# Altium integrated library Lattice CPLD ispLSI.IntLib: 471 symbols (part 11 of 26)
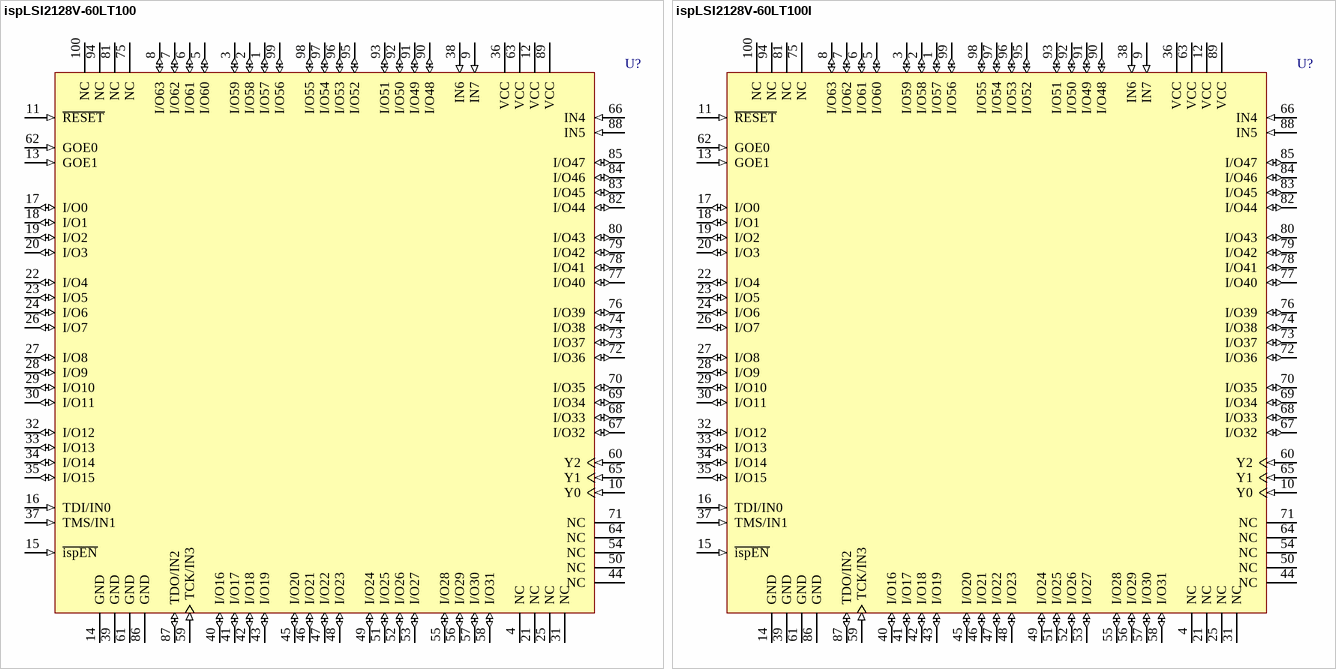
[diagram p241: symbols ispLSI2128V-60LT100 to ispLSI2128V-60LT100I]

## ispLSI2128V-60LT100I
designator U?
3.3V High-Density Programmable Logic
footprint TQFP100_N (Thin QFP, 100-Leads, Body 14x14mm, Pitch 0.5mm, IPC Medium Density)
footprint TQFP100_L (Thin QFP, 100-Leads, Body 14x14mm, Pitch 0.5mm, IPC High Density)
footprint TQFP100_M (Thin QFP, 100-Leads, Body 14x14mm, Pitch 0.5mm, IPC Low Density)
3D model 2128V-TQFP100 (100-Pin Thin Quad Flat Pack (TQFP100))
pins: 1 I/O57 (io), 2 I/O58 (io), 3 I/O59 (io), 4 NC, 5 I/O60 (io), 6 I/O61 (io), 7 I/O62 (io), 8 I/O63 (io), 9 IN7 (in), 10 Y0 (in), 11 ~{RESET} (in), 12 VCC (power), 13 GOE1 (in), 14 GND (power), 15 ~{ispEN} (in), 16 TDI/IN0 (in), 17 I/O0 (io), 18 I/O1 (io), 19 I/O2 (io), 20 I/O3 (io), 21 NC, 22 I/O4 (io), 23 I/O5 (io), 24 I/O6 (io), 25 NC, 26 I/O7 (io), 27 I/O8 (io), 28 I/O9 (io), 29 I/O10 (io), 30 I/O11 (io), 31 NC, 32 I/O12 (io), 33 I/O13 (io), 34 I/O14 (io), 35 I/O15 (io), 36 VCC (power), 37 TMS/IN1 (in), 38 IN6 (in), 39 GND (power), 40 I/O16 (io), 41 I/O17 (io), 42 I/O18 (io), 43 I/O19 (io), 44 NC, 45 I/O20 (io), 46 I/O21 (io), 47 I/O22 (io), 48 I/O23 (io), 49 I/O24 (io), 50 NC, 51 I/O25 (io), 52 I/O26 (io), 53 I/O27 (io), 54 NC, 55 I/O28 (io), 56 I/O29 (io), 57 I/O30 (io), 58 I/O31 (io), 59 TCK/IN3 (in), 60 Y2 (in), 61 GND (power), 62 GOE0 (in), 63 VCC (power), 64 NC, 65 Y1 (in), 66 IN4 (in), 67 I/O32 (io), 68 I/O33 (io), 69 I/O34 (io), 70 I/O35 (io), 71 NC, 72 I/O36 (io), 73 I/O37 (io), 74 I/O38 (io), 75 NC, 76 I/O39 (io), 77 I/O40 (io), 78 I/O41 (io), 79 I/O42 (io), 80 I/O43 (io), 81 NC, 82 I/O44 (io), 83 I/O45 (io), 84 I/O46 (io), 85 I/O47 (io), 86 GND (power), 87 TDO/IN2 (io), 88 IN5 (in), 89 VCC (power), 90 I/O48 (io), 91 I/O49 (io), 92 I/O50 (io), 93 I/O51 (io), 94 NC, 95 I/O52 (io), 96 I/O53 (io), 97 I/O54 (io), 98 I/O55 (io), 99 I/O56 (io), 100 NC

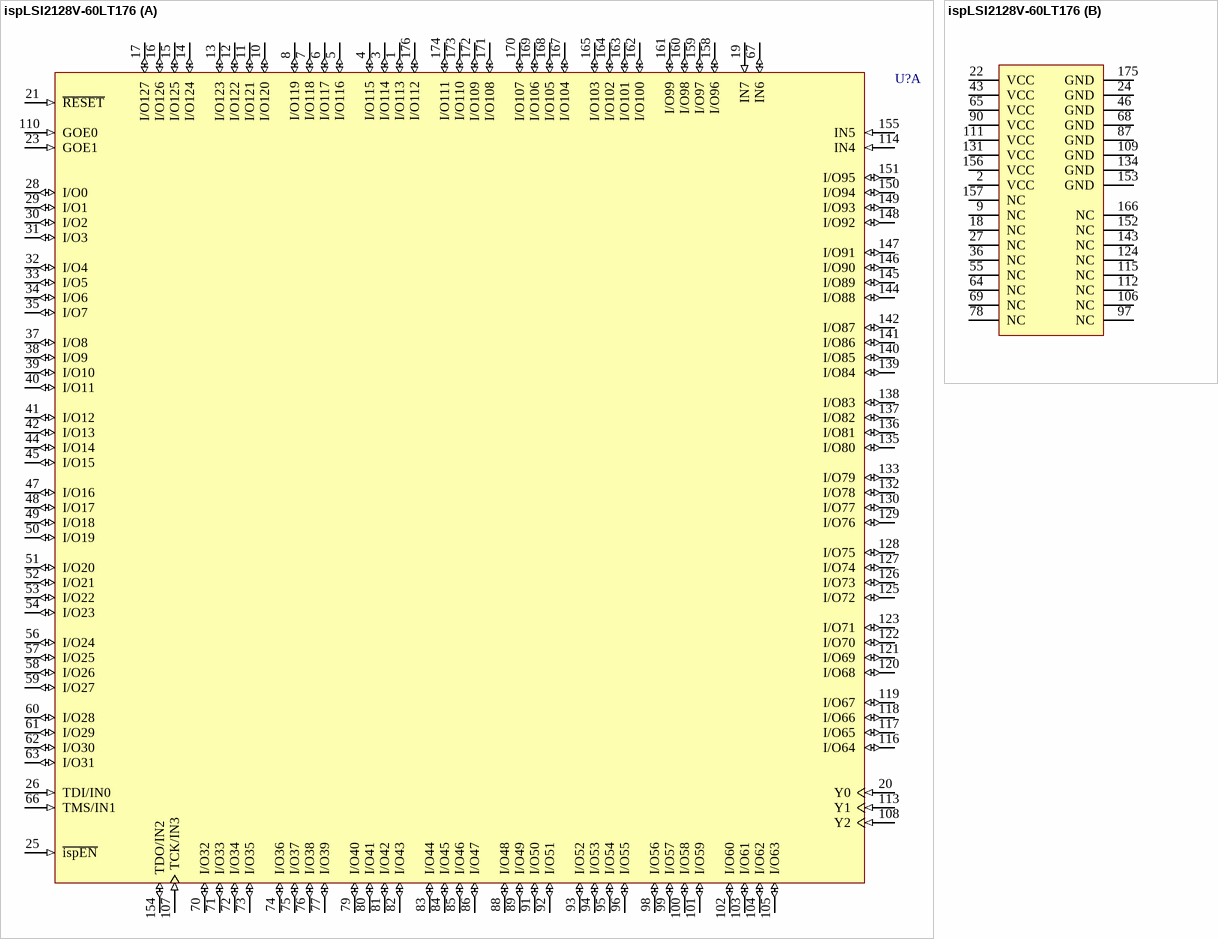
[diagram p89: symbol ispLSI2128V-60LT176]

## ispLSI2128V-60LT176
designator U?
3.3V High-Density Programmable Logic
footprint TQFP176_N (Thin QFP, 176-Leads, Body 24x24mm, Pitch 0.5mm, IPC Medium Density)
footprint TQFP176_L (Thin QFP, 176-Leads, Body 24x24mm, Pitch 0.5mm, IPC High Density)
footprint TQFP176_M (Thin QFP, 176-Leads, Body 24x24mm, Pitch 0.5mm, IPC Low Density)
3D model 2128V-TQFP176 (176-Pin Thin Quad Flat Pack 0.5 mm Pitch)
part A pins: 1 I/O113 (io), 3 I/O114 (io), 4 I/O115 (io), 5 I/O116 (io), 6 I/O117 (io), 7 I/O118 (io), 8 I/O119 (io), 10 I/O120 (io), 11 I/O121 (io), 12 I/O122 (io), 13 I/O123 (io), 14 I/O124 (io), 15 I/O125 (io), 16 I/O126 (io), 17 I/O127 (io), 19 IN7 (in), 20 Y0 (in), 21 ~{RESET} (in), 23 GOE1 (in), 25 ~{ispEN} (in), 26 TDI/IN0 (in), 28 I/O0 (io), 29 I/O1 (io), 30 I/O2 (io), 31 I/O3 (io), 32 I/O4 (io), 33 I/O5 (io), 34 I/O6 (io), 35 I/O7 (io), 37 I/O8 (io), 38 I/O9 (io), 39 I/O10 (io), 40 I/O11 (io), 41 I/O12 (io), 42 I/O13 (io), 44 I/O14 (io), 45 I/O15 (io), 47 I/O16 (io), 48 I/O17 (io), 49 I/O18 (io), 50 I/O19 (io), 51 I/O20 (io), 52 I/O21 (io), 53 I/O22 (io), 54 I/O23 (io), 56 I/O24 (io), 57 I/O25 (io), 58 I/O26 (io), 59 I/O27 (io), 60 I/O28 (io), 61 I/O29 (io), 62 I/O30 (io), 63 I/O31 (io), 66 TMS/IN1 (in), 67 IN6 (io), 70 I/O32 (io), 71 I/O33 (io), 72 I/O34 (io), 73 I/O35 (io), 74 I/O36 (io), 75 I/O37 (io), 76 I/O38 (io), 77 I/O39 (io), 79 I/O40 (io), 80 I/O41 (io), 81 I/O42 (io), 82 I/O43 (io), 83 I/O44 (io), 84 I/O45 (io), 85 I/O46 (io), 86 I/O47 (io), 88 I/O48 (io), 89 I/O49 (io), 91 I/O50 (io), 92 I/O51 (io), 93 I/O52 (io), 94 I/O53 (io), 95 I/O54 (io), 96 I/O55 (io), 98 I/O56 (io), 99 I/O57 (io), 100 I/O58 (io), 101 I/O59 (io), 102 I/O60 (io), 103 I/O61 (io), 104 I/O62 (io), 105 I/O63 (io), 107 TCK/IN3 (in), 108 Y2 (in), 110 GOE0 (in), 113 Y1 (in), 114 IN4 (in), 116 I/O64 (io), 117 I/O65 (io), 118 I/O66 (io), 119 I/O67 (io), 120 I/O68 (io), 121 I/O69 (io), 122 I/O70 (io), 123 I/O71 (io), 125 I/O72 (io), 126 I/O73 (io), 127 I/O74 (io), 128 I/O75 (io), 129 I/O76 (io), 130 I/O77 (io), 132 I/O78 (io), 133 I/O79 (io), 135 I/O80 (io), 136 I/O81 (io), 137 I/O82 (io), 138 I/O83 (io), 139 I/O84 (io), 140 I/O85 (io), 141 I/O86 (io), 142 I/O87 (io), 144 I/O88 (io), 145 I/O89 (io), 146 I/O90 (io), 147 I/O91 (io), 148 I/O92 (io), 149 I/O93 (io), 150 I/O94 (io), 151 I/O95 (io), 154 TDO/IN2 (io), 155 IN5 (in), 158 I/O96 (io), 159 I/O97 (io), 160 I/O98 (io), 161 I/O99 (io), 162 I/O100 (io), 163 I/O101 (io), 164 I/O102 (io), 165 I/O103 (io), 167 I/O104 (io), 168 I/O105 (io), 169 I/O106 (io), 170 I/O107 (io), 171 I/O108 (io), 172 I/O109 (io), 173 I/O110 (io), 174 I/O111 (io), 176 I/O112 (io)
part B pins: 2 VCC (power), 9 NC, 18 NC, 22 VCC (power), 24 GND (power), 27 NC, 36 NC, 43 VCC (power), 46 GND (power), 55 NC, 64 NC, 65 VCC (power), 68 GND (power), 69 NC, 78 NC, 87 GND (power), 90 VCC (power), 97 NC, 106 NC, 109 GND (power), 111 VCC (power), 112 NC, 115 NC, 124 NC, 131 VCC (power), 134 GND (power), 143 NC, 152 NC, 153 GND (power), 156 VCC (power), 157 NC, 166 NC, 175 GND (power)

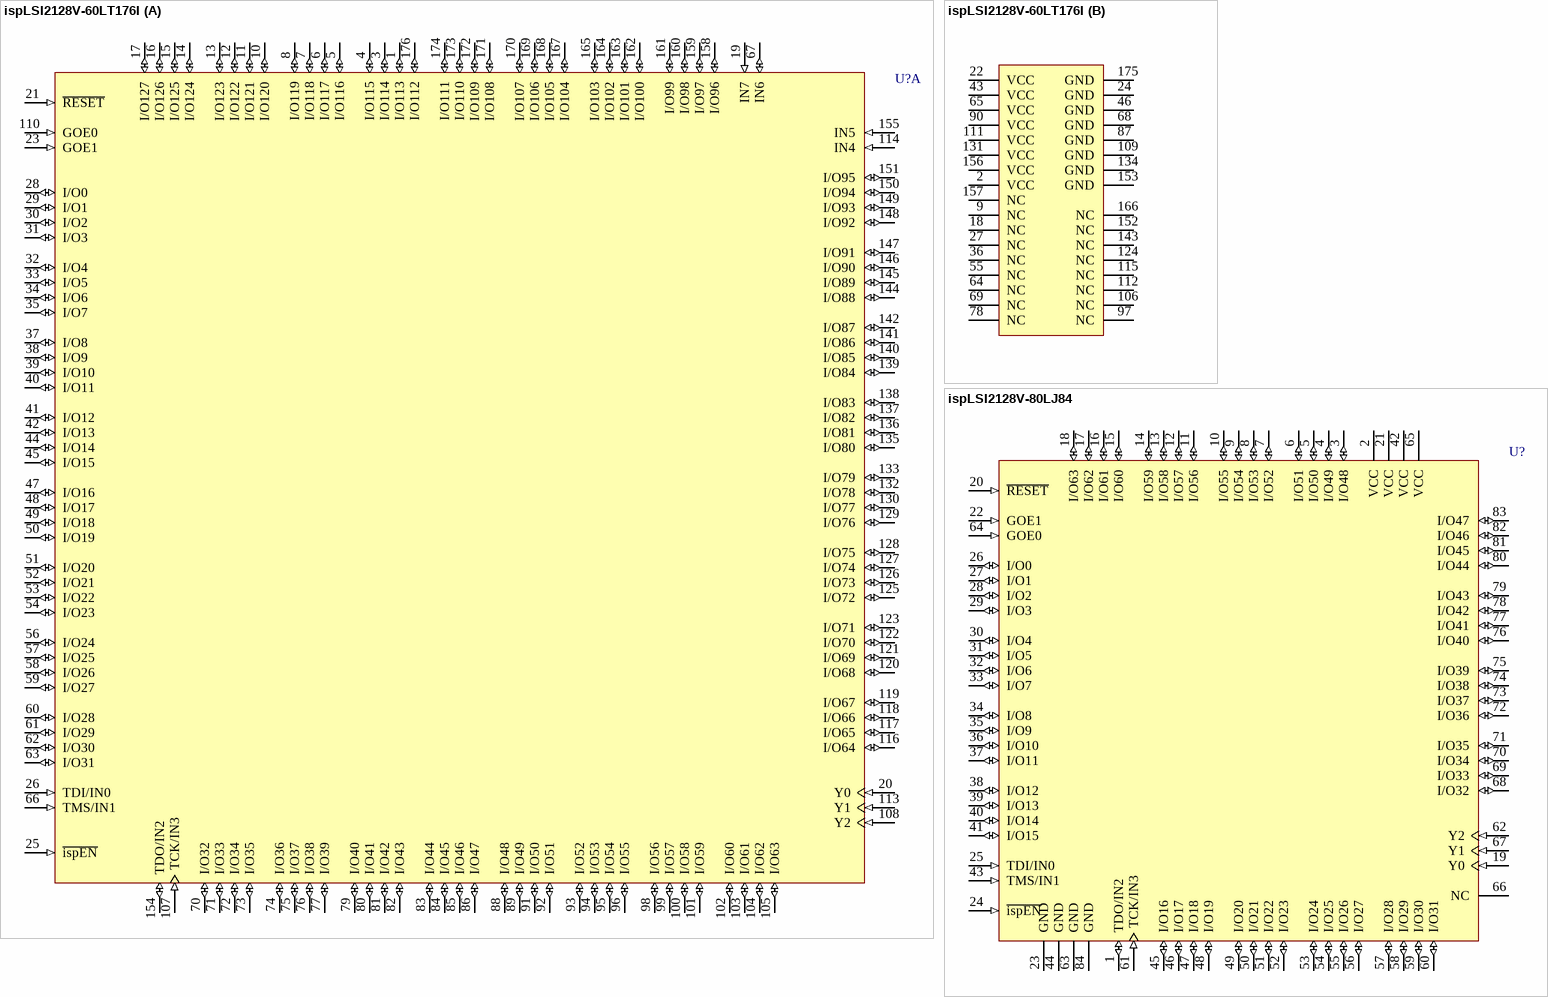
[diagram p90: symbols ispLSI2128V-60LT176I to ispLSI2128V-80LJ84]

## ispLSI2128V-60LT176I
designator U?
3.3V High-Density Programmable Logic
footprint TQFP176_N (Thin QFP, 176-Leads, Body 24x24mm, Pitch 0.5mm, IPC Medium Density)
footprint TQFP176_L (Thin QFP, 176-Leads, Body 24x24mm, Pitch 0.5mm, IPC High Density)
footprint TQFP176_M (Thin QFP, 176-Leads, Body 24x24mm, Pitch 0.5mm, IPC Low Density)
3D model 2128V-TQFP176 (176-Pin Thin Quad Flat Pack 0.5 mm Pitch)
part A pins: 1 I/O113 (io), 3 I/O114 (io), 4 I/O115 (io), 5 I/O116 (io), 6 I/O117 (io), 7 I/O118 (io), 8 I/O119 (io), 10 I/O120 (io), 11 I/O121 (io), 12 I/O122 (io), 13 I/O123 (io), 14 I/O124 (io), 15 I/O125 (io), 16 I/O126 (io), 17 I/O127 (io), 19 IN7 (in), 20 Y0 (in), 21 ~{RESET} (in), 23 GOE1 (in), 25 ~{ispEN} (in), 26 TDI/IN0 (in), 28 I/O0 (io), 29 I/O1 (io), 30 I/O2 (io), 31 I/O3 (io), 32 I/O4 (io), 33 I/O5 (io), 34 I/O6 (io), 35 I/O7 (io), 37 I/O8 (io), 38 I/O9 (io), 39 I/O10 (io), 40 I/O11 (io), 41 I/O12 (io), 42 I/O13 (io), 44 I/O14 (io), 45 I/O15 (io), 47 I/O16 (io), 48 I/O17 (io), 49 I/O18 (io), 50 I/O19 (io), 51 I/O20 (io), 52 I/O21 (io), 53 I/O22 (io), 54 I/O23 (io), 56 I/O24 (io), 57 I/O25 (io), 58 I/O26 (io), 59 I/O27 (io), 60 I/O28 (io), 61 I/O29 (io), 62 I/O30 (io), 63 I/O31 (io), 66 TMS/IN1 (in), 67 IN6 (io), 70 I/O32 (io), 71 I/O33 (io), 72 I/O34 (io), 73 I/O35 (io), 74 I/O36 (io), 75 I/O37 (io), 76 I/O38 (io), 77 I/O39 (io), 79 I/O40 (io), 80 I/O41 (io), 81 I/O42 (io), 82 I/O43 (io), 83 I/O44 (io), 84 I/O45 (io), 85 I/O46 (io), 86 I/O47 (io), 88 I/O48 (io), 89 I/O49 (io), 91 I/O50 (io), 92 I/O51 (io), 93 I/O52 (io), 94 I/O53 (io), 95 I/O54 (io), 96 I/O55 (io), 98 I/O56 (io), 99 I/O57 (io), 100 I/O58 (io), 101 I/O59 (io), 102 I/O60 (io), 103 I/O61 (io), 104 I/O62 (io), 105 I/O63 (io), 107 TCK/IN3 (in), 108 Y2 (in), 110 GOE0 (in), 113 Y1 (in), 114 IN4 (in), 116 I/O64 (io), 117 I/O65 (io), 118 I/O66 (io), 119 I/O67 (io), 120 I/O68 (io), 121 I/O69 (io), 122 I/O70 (io), 123 I/O71 (io), 125 I/O72 (io), 126 I/O73 (io), 127 I/O74 (io), 128 I/O75 (io), 129 I/O76 (io), 130 I/O77 (io), 132 I/O78 (io), 133 I/O79 (io), 135 I/O80 (io), 136 I/O81 (io), 137 I/O82 (io), 138 I/O83 (io), 139 I/O84 (io), 140 I/O85 (io), 141 I/O86 (io), 142 I/O87 (io), 144 I/O88 (io), 145 I/O89 (io), 146 I/O90 (io), 147 I/O91 (io), 148 I/O92 (io), 149 I/O93 (io), 150 I/O94 (io), 151 I/O95 (io), 154 TDO/IN2 (io), 155 IN5 (in), 158 I/O96 (io), 159 I/O97 (io), 160 I/O98 (io), 161 I/O99 (io), 162 I/O100 (io), 163 I/O101 (io), 164 I/O102 (io), 165 I/O103 (io), 167 I/O104 (io), 168 I/O105 (io), 169 I/O106 (io), 170 I/O107 (io), 171 I/O108 (io), 172 I/O109 (io), 173 I/O110 (io), 174 I/O111 (io), 176 I/O112 (io)
part B pins: 2 VCC (power), 9 NC, 18 NC, 22 VCC (power), 24 GND (power), 27 NC, 36 NC, 43 VCC (power), 46 GND (power), 55 NC, 64 NC, 65 VCC (power), 68 GND (power), 69 NC, 78 NC, 87 GND (power), 90 VCC (power), 97 NC, 106 NC, 109 GND (power), 111 VCC (power), 112 NC, 115 NC, 124 NC, 131 VCC (power), 134 GND (power), 143 NC, 152 NC, 153 GND (power), 156 VCC (power), 157 NC, 166 NC, 175 GND (power)

## ispLSI2128V-80LJ84
designator U?
3.3V High-Density Programmable Logic
footprint PLCC84_N (Leaded Chip Carrier, 84-Leads, Body 29.3x29.3mm, Pitch 1.27mm, IPC Medium Density)
footprint PLCC84_L (Leaded Chip Carrier, 84-Leads, Body 29.3x29.3mm, Pitch 1.27mm, IPC High Density)
footprint PLCC84_M (Leaded Chip Carrier, 84-Leads, Body 29.3x29.3mm, Pitch 1.27mm, IPC Low Density)
3D model 2128V-PLCC84 (84-Pin Leaded Chip Carrier 1.27 mm Pitch)
pins: 1 TDO/IN2 (io), 2 VCC (power), 3 I/O48 (io), 4 I/O49 (io), 5 I/O50 (io), 6 I/O51 (io), 7 I/O52 (io), 8 I/O53 (io), 9 I/O54 (io), 10 I/O55 (io), 11 I/O56 (io), 12 I/O57 (io), 13 I/O58 (io), 14 I/O59 (io), 15 I/O60 (io), 16 I/O61 (io), 17 I/O62 (io), 18 I/O63 (io), 19 Y0 (in), 20 ~{RESET} (in), 21 VCC (power), 22 GOE1 (in), 23 GND (power), 24 ~{isp}~{EN} (in), 25 TDI/IN0 (in), 26 I/O0 (io), 27 I/O1 (io), 28 I/O2 (io), 29 I/O3 (io), 30 I/O4 (io), 31 I/O5 (io), 32 I/O6 (io), 33 I/O7 (io), 34 I/O8 (io), 35 I/O9 (io), 36 I/O10 (io), 37 I/O11 (io), 38 I/O12 (io), 39 I/O13 (io), 40 I/O14 (io), 41 I/O15 (io), 42 VCC (power), 43 TMS/IN1 (in), 44 GND (power), 45 I/O16 (io), 46 I/O17 (io), 47 I/O18 (io), 48 I/O19 (io), 49 I/O20 (io), 50 I/O21 (io), 51 I/O22 (io), 52 I/O23 (io), 53 I/O24 (io), 54 I/O25 (io), 55 I/O26 (io), 56 I/O27 (io), 57 I/O28 (io), 58 I/O29 (io), 59 I/O30 (io), 60 I/O31 (io), 61 TCK/IN3 (in), 62 Y2 (in), 63 GND (power), 64 GOE0 (in), 65 VCC (power), 66 NC, 67 Y1 (in), 68 I/O32 (io), 69 I/O33 (io), 70 I/O34 (io), 71 I/O35 (io), 72 I/O36 (io), 73 I/O37 (io), 74 I/O38 (io), 75 I/O39 (io), 76 I/O40 (io), 77 I/O41 (io), 78 I/O42 (io), 79 I/O43 (io), 80 I/O44 (io), 81 I/O45 (io), 82 I/O46 (io), 83 I/O47 (io), 84 GND (power)

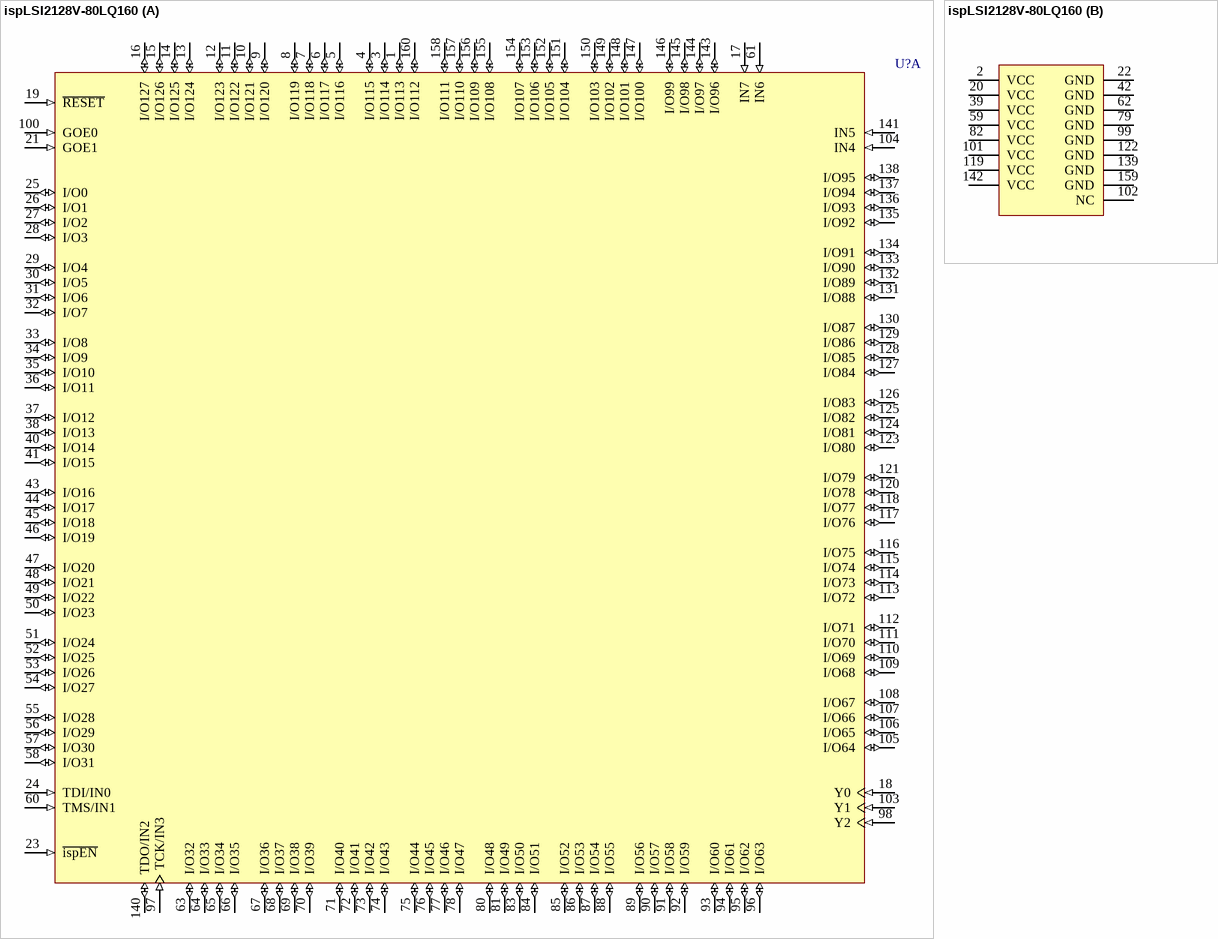
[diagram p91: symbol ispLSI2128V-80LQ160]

## ispLSI2128V-80LQ160
designator U?
3.3V High-Density Programmable Logic
footprint PQFP160_N (QFP, 160-Leads, Body 28 x 28mm, Pitch 0.65mm, IPC Medium Density)
footprint PQFP160_L (QFP, 160-Leads, Body 28 x 28mm, Pitch 0.65mm, IPC High Density)
footprint PQFP160_M (QFP, 160-Leads, Body 28 x 28mm, Pitch 0.65mm, IPC Low Density)
3D model 2128V-PQFP160 (160-Pin Quad Flat Pack 0.65 mm Pitch)
part A pins: 1 I/O113 (io), 3 I/O114 (io), 4 I/O115 (io), 5 I/O116 (io), 6 I/O117 (io), 7 I/O118 (io), 8 I/O119 (io), 9 I/O120 (io), 10 I/O121 (io), 11 I/O122 (io), 12 I/O123 (io), 13 I/O124 (io), 14 I/O125 (io), 15 I/O126 (io), 16 I/O127 (io), 17 IN7 (in), 18 Y0 (in), 19 ~{RESET} (in), 21 GOE1 (in), 23 ~{ispEN} (in), 24 TDI/IN0 (in), 25 I/O0 (io), 26 I/O1 (io), 27 I/O2 (io), 28 I/O3 (io), 29 I/O4 (io), 30 I/O5 (io), 31 I/O6 (io), 32 I/O7 (io), 33 I/O8 (io), 34 I/O9 (io), 35 I/O10 (io), 36 I/O11 (io), 37 I/O12 (io), 38 I/O13 (io), 40 I/O14 (io), 41 I/O15 (io), 43 I/O16 (io), 44 I/O17 (io), 45 I/O18 (io), 46 I/O19 (io), 47 I/O20 (io), 48 I/O21 (io), 49 I/O22 (io), 50 I/O23 (io), 51 I/O24 (io), 52 I/O25 (io), 53 I/O26 (io), 54 I/O27 (io), 55 I/O28 (io), 56 I/O29 (io), 57 I/O30 (io), 58 I/O31 (io), 60 TMS/IN1 (in), 61 IN6 (in), 63 I/O32 (io), 64 I/O33 (io), 65 I/O34 (io), 66 I/O35 (io), 67 I/O36 (io), 68 I/O37 (io), 69 I/O38 (io), 70 I/O39 (io), 71 I/O40 (io), 72 I/O41 (io), 73 I/O42 (io), 74 I/O43 (io), 75 I/O44 (io), 76 I/O45 (io), 77 I/O46 (io), 78 I/O47 (io), 80 I/O48 (io), 81 I/O49 (io), 83 I/O50 (io), 84 I/O51 (io), 85 I/O52 (io), 86 I/O53 (io), 87 I/O54 (io), 88 I/O55 (io), 89 I/O56 (io), 90 I/O57 (io), 91 I/O58 (io), 92 I/O59 (io), 93 I/O60 (io), 94 I/O61 (io), 95 I/O62 (io), 96 I/O63 (io), 97 TCK/IN3 (in), 98 Y2 (in), 100 GOE0 (in), 103 Y1 (in), 104 IN4 (in), 105 I/O64 (io), 106 I/O65 (io), 107 I/O66 (io), 108 I/O67 (io), 109 I/O68 (io), 110 I/O69 (io), 111 I/O70 (io), 112 I/O71 (io), 113 I/O72 (io), 114 I/O73 (io), 115 I/O74 (io), 116 I/O75 (io), 117 I/O76 (io), 118 I/O77 (io), 120 I/O78 (io), 121 I/O79 (io), 123 I/O80 (io), 124 I/O81 (io), 125 I/O82 (io), 126 I/O83 (io), 127 I/O84 (io), 128 I/O85 (io), 129 I/O86 (io), 130 I/O87 (io), 131 I/O88 (io), 132 I/O89 (io), 133 I/O90 (io), 134 I/O91 (io), 135 I/O92 (io), 136 I/O93 (io), 137 I/O94 (io), 138 I/O95 (io), 140 TDO/IN2 (io), 141 IN5 (in), 143 I/O96 (io), 144 I/O97 (io), 145 I/O98 (io), 146 I/O99 (io), 147 I/O100 (io), 148 I/O101 (io), 149 I/O102 (io), 150 I/O103 (io), 151 I/O104 (io), 152 I/O105 (io), 153 I/O106 (io), 154 I/O107 (io), 155 I/O108 (io), 156 I/O109 (io), 157 I/O110 (io), 158 I/O111 (io), 160 I/O112 (io)
part B pins: 2 VCC (power), 20 VCC (power), 22 GND (power), 39 VCC (power), 42 GND (power), 59 VCC (power), 62 GND (power), 79 GND (power), 82 VCC (power), 99 GND (power), 101 VCC (power), 102 NC, 119 VCC (power), 122 GND (power), 139 GND (power), 142 VCC (power), 159 GND (power)

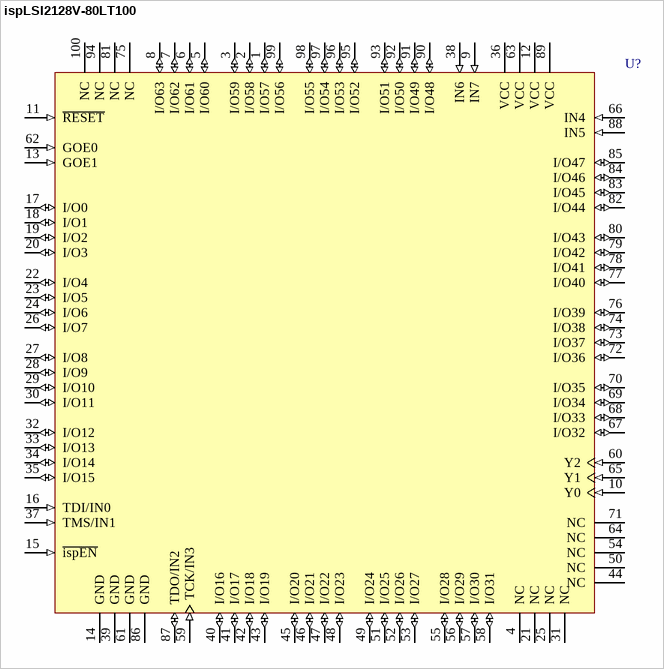
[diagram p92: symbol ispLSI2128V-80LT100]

## ispLSI2128V-80LT100
designator U?
3.3V High-Density Programmable Logic
footprint TQFP100_N (Thin QFP, 100-Leads, Body 14x14mm, Pitch 0.5mm, IPC Medium Density)
footprint TQFP100_L (Thin QFP, 100-Leads, Body 14x14mm, Pitch 0.5mm, IPC High Density)
footprint TQFP100_M (Thin QFP, 100-Leads, Body 14x14mm, Pitch 0.5mm, IPC Low Density)
3D model 2128V-TQFP100 (100-Pin Thin Quad Flat Pack (TQFP100))
pins: 1 I/O57 (io), 2 I/O58 (io), 3 I/O59 (io), 4 NC, 5 I/O60 (io), 6 I/O61 (io), 7 I/O62 (io), 8 I/O63 (io), 9 IN7 (in), 10 Y0 (in), 11 ~{RESET} (in), 12 VCC (power), 13 GOE1 (in), 14 GND (power), 15 ~{ispEN} (in), 16 TDI/IN0 (in), 17 I/O0 (io), 18 I/O1 (io), 19 I/O2 (io), 20 I/O3 (io), 21 NC, 22 I/O4 (io), 23 I/O5 (io), 24 I/O6 (io), 25 NC, 26 I/O7 (io), 27 I/O8 (io), 28 I/O9 (io), 29 I/O10 (io), 30 I/O11 (io), 31 NC, 32 I/O12 (io), 33 I/O13 (io), 34 I/O14 (io), 35 I/O15 (io), 36 VCC (power), 37 TMS/IN1 (in), 38 IN6 (in), 39 GND (power), 40 I/O16 (io), 41 I/O17 (io), 42 I/O18 (io), 43 I/O19 (io), 44 NC, 45 I/O20 (io), 46 I/O21 (io), 47 I/O22 (io), 48 I/O23 (io), 49 I/O24 (io), 50 NC, 51 I/O25 (io), 52 I/O26 (io), 53 I/O27 (io), 54 NC, 55 I/O28 (io), 56 I/O29 (io), 57 I/O30 (io), 58 I/O31 (io), 59 TCK/IN3 (in), 60 Y2 (in), 61 GND (power), 62 GOE0 (in), 63 VCC (power), 64 NC, 65 Y1 (in), 66 IN4 (in), 67 I/O32 (io), 68 I/O33 (io), 69 I/O34 (io), 70 I/O35 (io), 71 NC, 72 I/O36 (io), 73 I/O37 (io), 74 I/O38 (io), 75 NC, 76 I/O39 (io), 77 I/O40 (io), 78 I/O41 (io), 79 I/O42 (io), 80 I/O43 (io), 81 NC, 82 I/O44 (io), 83 I/O45 (io), 84 I/O46 (io), 85 I/O47 (io), 86 GND (power), 87 TDO/IN2 (io), 88 IN5 (in), 89 VCC (power), 90 I/O48 (io), 91 I/O49 (io), 92 I/O50 (io), 93 I/O51 (io), 94 NC, 95 I/O52 (io), 96 I/O53 (io), 97 I/O54 (io), 98 I/O55 (io), 99 I/O56 (io), 100 NC

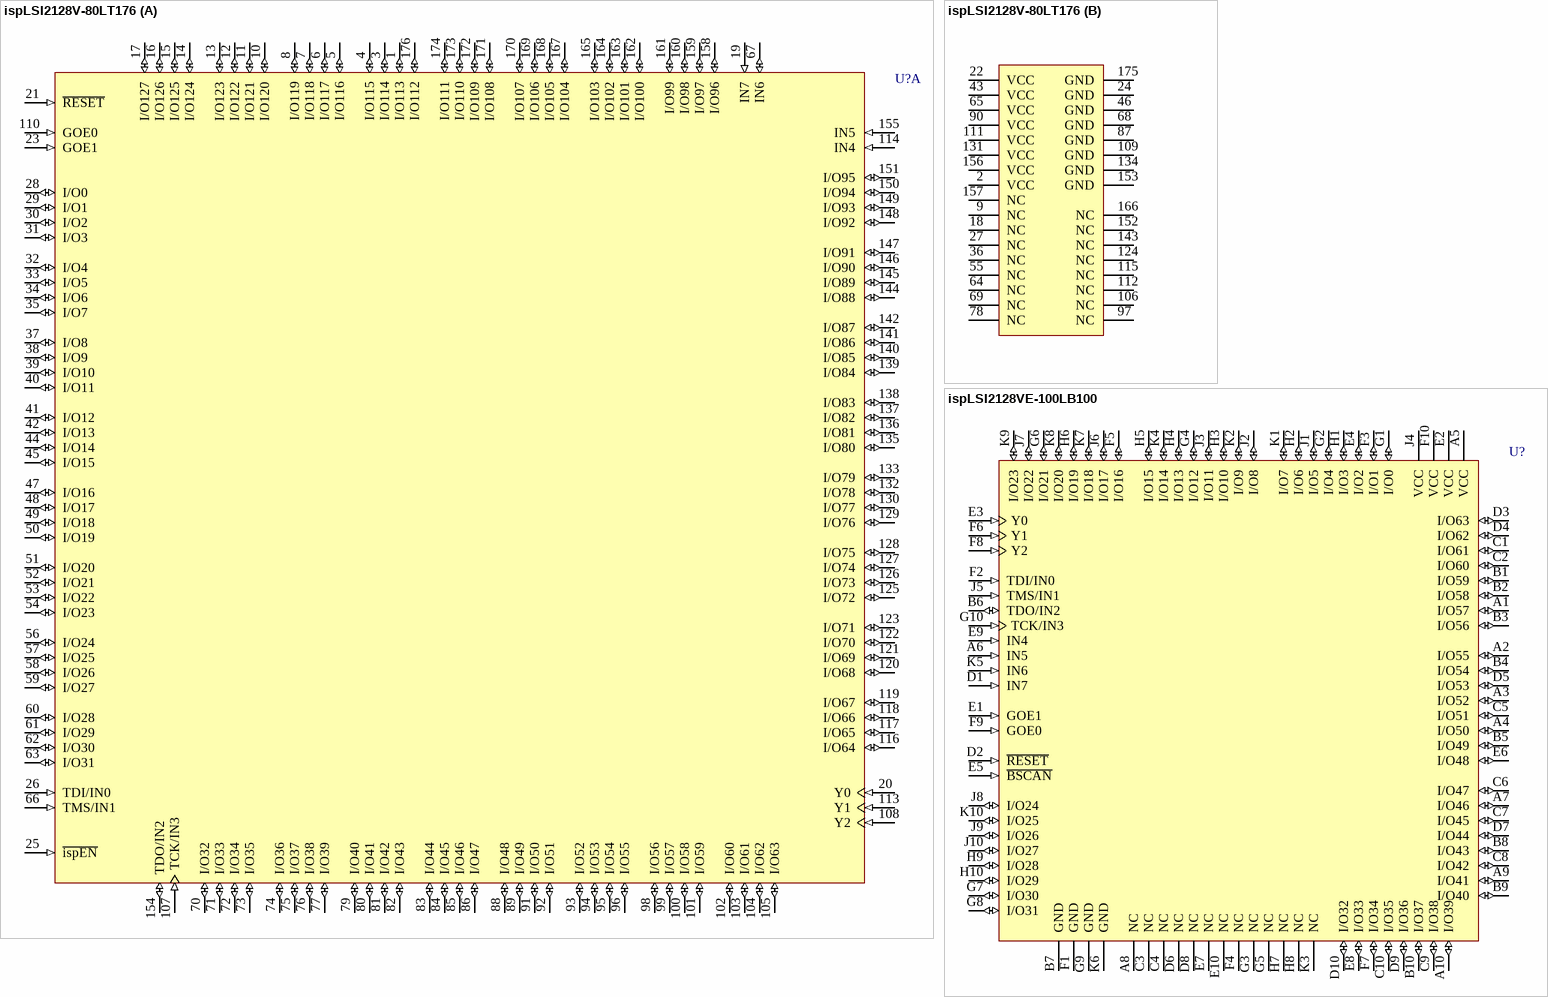
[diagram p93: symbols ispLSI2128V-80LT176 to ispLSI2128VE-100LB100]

## ispLSI2128V-80LT176
designator U?
3.3V High-Density Programmable Logic
footprint TQFP176_N (Thin QFP, 176-Leads, Body 24x24mm, Pitch 0.5mm, IPC Medium Density)
footprint TQFP176_L (Thin QFP, 176-Leads, Body 24x24mm, Pitch 0.5mm, IPC High Density)
footprint TQFP176_M (Thin QFP, 176-Leads, Body 24x24mm, Pitch 0.5mm, IPC Low Density)
3D model 2128V-TQFP176 (176-Pin Thin Quad Flat Pack 0.5 mm Pitch)
part A pins: 1 I/O113 (io), 3 I/O114 (io), 4 I/O115 (io), 5 I/O116 (io), 6 I/O117 (io), 7 I/O118 (io), 8 I/O119 (io), 10 I/O120 (io), 11 I/O121 (io), 12 I/O122 (io), 13 I/O123 (io), 14 I/O124 (io), 15 I/O125 (io), 16 I/O126 (io), 17 I/O127 (io), 19 IN7 (in), 20 Y0 (in), 21 ~{RESET} (in), 23 GOE1 (in), 25 ~{ispEN} (in), 26 TDI/IN0 (in), 28 I/O0 (io), 29 I/O1 (io), 30 I/O2 (io), 31 I/O3 (io), 32 I/O4 (io), 33 I/O5 (io), 34 I/O6 (io), 35 I/O7 (io), 37 I/O8 (io), 38 I/O9 (io), 39 I/O10 (io), 40 I/O11 (io), 41 I/O12 (io), 42 I/O13 (io), 44 I/O14 (io), 45 I/O15 (io), 47 I/O16 (io), 48 I/O17 (io), 49 I/O18 (io), 50 I/O19 (io), 51 I/O20 (io), 52 I/O21 (io), 53 I/O22 (io), 54 I/O23 (io), 56 I/O24 (io), 57 I/O25 (io), 58 I/O26 (io), 59 I/O27 (io), 60 I/O28 (io), 61 I/O29 (io), 62 I/O30 (io), 63 I/O31 (io), 66 TMS/IN1 (in), 67 IN6 (io), 70 I/O32 (io), 71 I/O33 (io), 72 I/O34 (io), 73 I/O35 (io), 74 I/O36 (io), 75 I/O37 (io), 76 I/O38 (io), 77 I/O39 (io), 79 I/O40 (io), 80 I/O41 (io), 81 I/O42 (io), 82 I/O43 (io), 83 I/O44 (io), 84 I/O45 (io), 85 I/O46 (io), 86 I/O47 (io), 88 I/O48 (io), 89 I/O49 (io), 91 I/O50 (io), 92 I/O51 (io), 93 I/O52 (io), 94 I/O53 (io), 95 I/O54 (io), 96 I/O55 (io), 98 I/O56 (io), 99 I/O57 (io), 100 I/O58 (io), 101 I/O59 (io), 102 I/O60 (io), 103 I/O61 (io), 104 I/O62 (io), 105 I/O63 (io), 107 TCK/IN3 (in), 108 Y2 (in), 110 GOE0 (in), 113 Y1 (in), 114 IN4 (in), 116 I/O64 (io), 117 I/O65 (io), 118 I/O66 (io), 119 I/O67 (io), 120 I/O68 (io), 121 I/O69 (io), 122 I/O70 (io), 123 I/O71 (io), 125 I/O72 (io), 126 I/O73 (io), 127 I/O74 (io), 128 I/O75 (io), 129 I/O76 (io), 130 I/O77 (io), 132 I/O78 (io), 133 I/O79 (io), 135 I/O80 (io), 136 I/O81 (io), 137 I/O82 (io), 138 I/O83 (io), 139 I/O84 (io), 140 I/O85 (io), 141 I/O86 (io), 142 I/O87 (io), 144 I/O88 (io), 145 I/O89 (io), 146 I/O90 (io), 147 I/O91 (io), 148 I/O92 (io), 149 I/O93 (io), 150 I/O94 (io), 151 I/O95 (io), 154 TDO/IN2 (io), 155 IN5 (in), 158 I/O96 (io), 159 I/O97 (io), 160 I/O98 (io), 161 I/O99 (io), 162 I/O100 (io), 163 I/O101 (io), 164 I/O102 (io), 165 I/O103 (io), 167 I/O104 (io), 168 I/O105 (io), 169 I/O106 (io), 170 I/O107 (io), 171 I/O108 (io), 172 I/O109 (io), 173 I/O110 (io), 174 I/O111 (io), 176 I/O112 (io)
part B pins: 2 VCC (power), 9 NC, 18 NC, 22 VCC (power), 24 GND (power), 27 NC, 36 NC, 43 VCC (power), 46 GND (power), 55 NC, 64 NC, 65 VCC (power), 68 GND (power), 69 NC, 78 NC, 87 GND (power), 90 VCC (power), 97 NC, 106 NC, 109 GND (power), 111 VCC (power), 112 NC, 115 NC, 124 NC, 131 VCC (power), 134 GND (power), 143 NC, 152 NC, 153 GND (power), 156 VCC (power), 157 NC, 166 NC, 175 GND (power)

## ispLSI2128VE-100LB100
designator U?
3.3V In-System Programmable SuperFAST High Density PLD
footprint caBGA100 (BGA, 100-Leads, Body 10x10mm, Pitch 0.8mm)
3D model 2128VE-caBGA100 (100-Ball Chip Array Ball Grid Array (caBGA100))
pins: A1 I/O57 (io), A2 I/O55 (io), A3 I/O52 (io), A4 I/O50 (io), A5 VCC (power), A6 IN5 (in), A7 I/O46 (io), A8 NC, A9 I/O41 (io), A10 I/O39 (io), B1 I/O59 (io), B2 I/O58 (io), B3 I/O56 (io), B4 I/O54 (io), B5 I/O49 (io), B6 TDO/IN2 (io), B7 GND (power), B8 I/O43 (io), B9 I/O40 (io), B10 I/O37 (io), C1 I/O61 (io), C2 I/O60 (io), C3 NC, C4 NC, C5 I/O51 (io), C6 I/O47 (io), C7 I/O45 (io), C8 I/O42 (io), C9 I/O38 (io), C10 I/O35 (io), D1 IN7 (in), D2 ~{RESET} (in), D3 I/O63 (io), D4 I/O62 (io), D5 I/O53 (io), D6 NC, D7 I/O44 (io), D8 NC, D9 I/O36 (io), D10 I/O32 (io), E1 GOE1 (in), E2 VCC (power), E3 Y0 (in), E4 I/O2 (io), E5 ~{BSCAN} (in), E6 I/O48 (io), E7 NC, E8 I/O33 (io), E9 IN4 (in), E10 NC, F1 GND (power), F2 TDI/IN0 (in), F3 I/O1 (io), F4 NC, F5 I/O16 (io), F6 Y1 (in), F7 I/O34 (io), F8 Y2 (in), F9 GOE0 (in), F10 VCC (power), G1 I/O0 (io), G2 I/O4 (io), G3 NC, G4 I/O12 (io), G5 NC, G6 I/O21 (io), G7 I/O30 (io), G8 I/O31 (io), G9 GND (power), G10 TCK/IN3 (in), H1 I/O3 (io), H2 I/O6 (io), H3 I/O10 (io), H4 I/O13 (io), H5 I/O15 (io), H6 I/O19 (io), H7 NC, H8 NC, H9 I/O28 (io), H10 I/O29 (io), J1 I/O5 (io), J2 I/O8 (io), J3 I/O11 (io), J4 VCC (power), J5 TMS/IN1 (in), J6 I/O17 (io), J7 I/O22 (io), J8 I/O24 (io), J9 I/O26 (io), J10 I/O27 (io), K1 I/O7 (io), K2 I/O9 (io), K3 NC, K4 I/O14 (io), K5 IN6 (in), K6 GND (power), K7 I/O18 (io), K8 I/O20 (io), K9 I/O23 (io), K10 I/O25 (io)

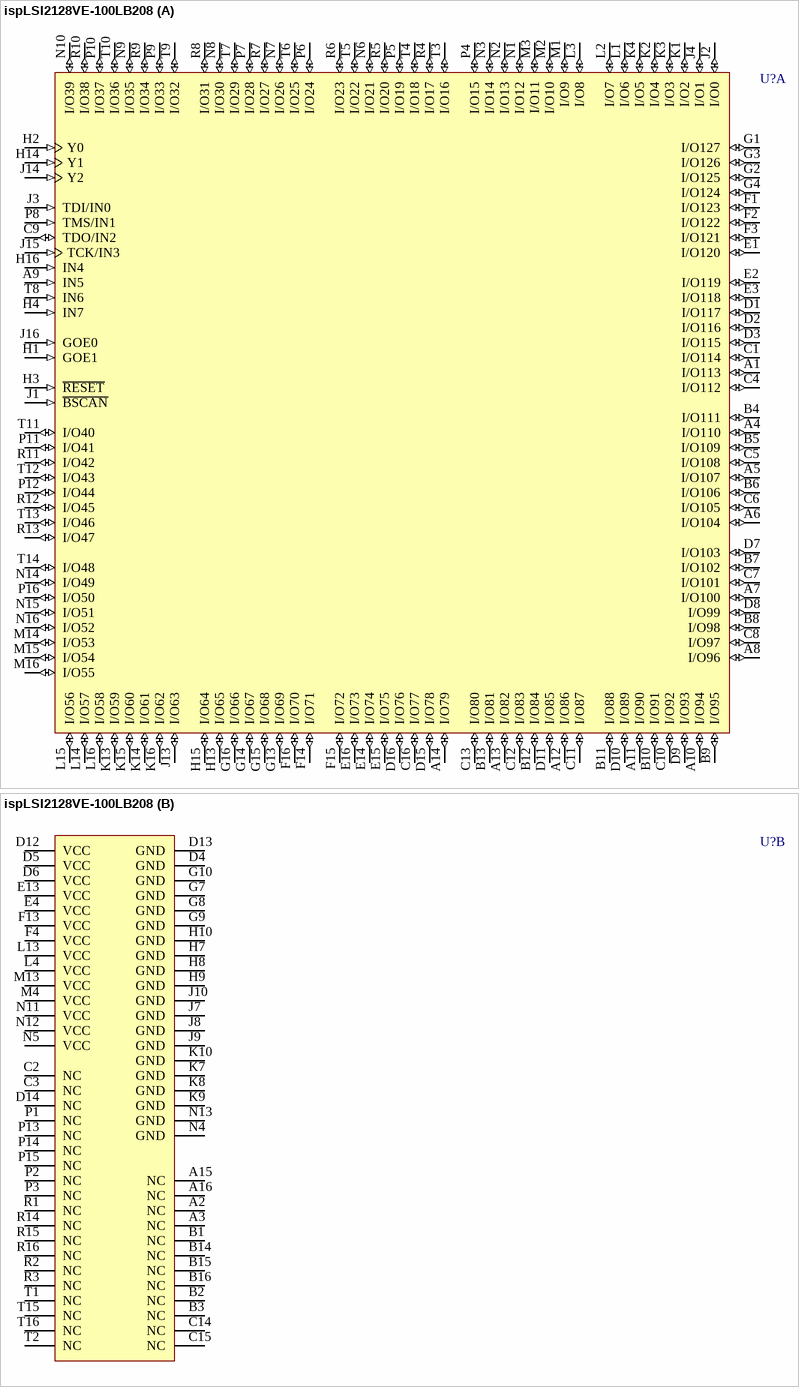
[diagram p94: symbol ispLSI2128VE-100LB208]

## ispLSI2128VE-100LB208
designator U?
3.3V In-System Programmable SuperFAST High Density PLD
footprint fpBGA208 (BGA, 208-Leads, Body 17x17mm, Pitch 1mm)
3D model 2128VE-fpBGA208 (208-Ball Fine Pitch Ball Grid Array (fpBGA208))
part A pins: A1 I/O113 (io), A4 I/O110 (io), A5 I/O107 (io), A6 I/O104 (io), A7 I/O100 (io), A8 I/O96 (io), A9 IN5 (in), A10 I/O94 (io), A11 I/O90 (io), A12 I/O86 (io), A13 I/O82 (io), A14 I/O79 (io), B4 I/O111 (io), B5 I/O109 (io), B6 I/O106 (io), B7 I/O102 (io), B8 I/O98 (io), B9 I/O95 (io), B10 I/O91 (io), B11 I/O88 (io), B12 I/O84 (io), B13 I/O81 (io), C1 I/O114 (io), C4 I/O112 (io), C5 I/O108 (io), C6 I/O105 (io), C7 I/O101 (io), C8 I/O97 (io), C9 TDO/IN2 (io), C10 I/O92 (io), C11 I/O87 (io), C12 I/O83 (io), C13 I/O80 (io), C16 I/O77 (io), D1 I/O117 (io), D2 I/O116 (io), D3 I/O115 (io), D7 I/O103 (io), D8 I/O99 (io), D9 I/O93 (io), D10 I/O89 (io), D11 I/O85 (io), D15 I/O78 (io), D16 I/O76 (io), E1 I/O120 (io), E2 I/O119 (io), E3 I/O118 (io), E14 I/O74 (io), E15 I/O75 (io), E16 I/O73 (io), F1 I/O123 (io), F2 I/O122 (io), F3 I/O121 (io), F14 I/O71 (io), F15 I/O72 (io), F16 I/O70 (io), G1 I/O127 (io), G2 I/O125 (io), G3 I/O126 (io), G4 I/O124 (io), G13 I/O69 (io), G14 I/O67 (io), G15 I/O68 (io), G16 I/O66 (io), H1 GOE1 (in), H2 Y0 (in), H3 ~{RESET} (in), H4 IN7 (in), H13 I/O65 (io), H14 Y1 (in), H15 I/O64 (io), H16 IN4 (in), J1 ~{BSCAN} (in), J2 I/O0 (io), J3 TDI/IN0 (in), J4 I/O1 (io), J13 I/O63 (io), J14 Y2 (in), J15 TCK/IN3 (in), J16 GOE0 (in), K1 I/O2 (io), K2 I/O4 (io), K3 I/O3 (io), K4 I/O5 (io), K13 I/O59 (io), K14 I/O61 (io), K15 I/O60 (io), K16 I/O62 (io), L1 I/O6 (io), L2 I/O7 (io), L3 I/O8 (io), L14 I/O57 (io), L15 I/O56 (io), L16 I/O58 (io), M1 I/O9 (io), M2 I/O10 (io), M3 I/O11 (io), M14 I/O53 (io), M15 I/O54 (io), M16 I/O55 (io), N1 I/O12 (io), N2 I/O13 (io), N3 I/O14 (io), N6 I/O21 (io), N7 I/O26 (io), N8 I/O30 (io), N9 I/O35 (io), N10 I/O39 (io), N14 I/O49 (io), N15 I/O51 (io), N16 I/O52 (io), P4 I/O15 (io), P5 I/O19 (io), P6 I/O24 (io), P7 I/O28 (io), P8 TMS/IN1 (in), P9 I/O33 (io), P10 I/O37 (io), P11 I/O41 (io), P12 I/O44 (io), P16 I/O50 (io), R4 I/O17 (io), R5 I/O20 (io), R6 I/O23 (io), R7 I/O27 (io), R8 I/O31 (io), R9 I/O34 (io), R10 I/O38 (io), R11 I/O42 (io), R12 I/O45 (io), R13 I/O47 (io), T3 I/O16 (io), T4 I/O18 (io), T5 I/O22 (io), T6 I/O25 (io), T7 I/O29 (io), T8 IN6 (in), T9 I/O32 (io), T10 I/O36 (io), T11 I/O40 (io), T12 I/O43 (io), T13 I/O46 (io), T14 I/O48 (io)
part B pins: A2 NC, A3 NC, A15 NC, A16 NC, B1 NC, B2 NC, B3 NC, B14 NC, B15 NC, B16 NC, C2 NC, C3 NC, C14 NC, C15 NC, D4 GND (power), D5 VCC (power), D6 VCC (power), D12 VCC (power), D13 GND (power), D14 NC, E4 VCC (power), E13 VCC (power), F4 VCC (power), F13 VCC (power), G7 GND (power), G8 GND (power), G9 GND (power), G10 GND (power), H7 GND (power), H8 GND (power), H9 GND (power), H10 GND (power), J7 GND (power), J8 GND (power), J9 GND (power), J10 GND (power), K7 GND (power), K8 GND (power), K9 GND (power), K10 GND (power), L4 VCC (power), L13 VCC (power), M4 VCC (power), M13 VCC (power), N4 GND (power), N5 VCC (power), N11 VCC (power), N12 VCC (power), N13 GND (power), P1 NC, P2 NC, P3 NC, P13 NC, P14 NC, P15 NC, R1 NC, R2 NC, R3 NC, R14 NC, R15 NC, R16 NC, T1 NC, T2 NC, T15 NC, T16 NC

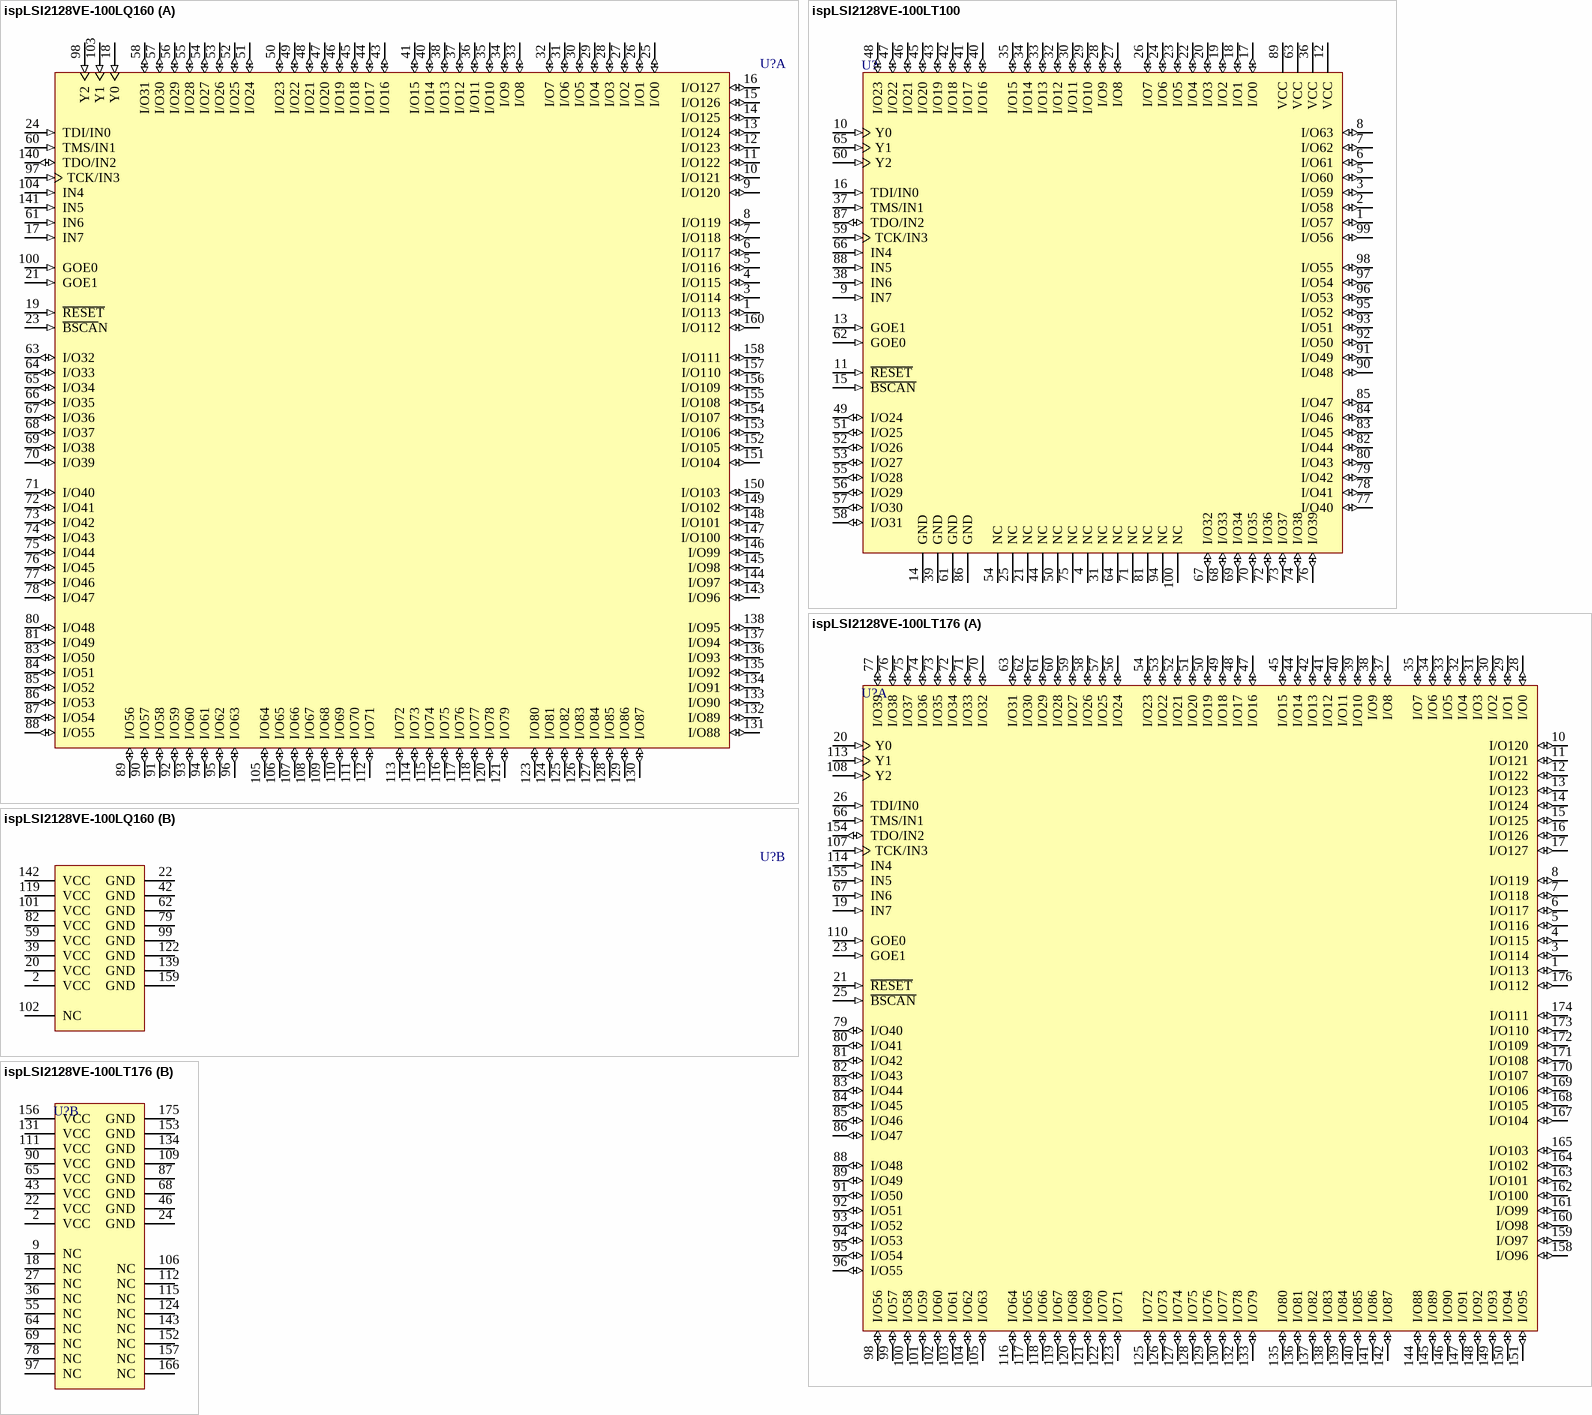
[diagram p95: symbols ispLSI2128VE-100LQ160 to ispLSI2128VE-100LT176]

## ispLSI2128VE-100LQ160
designator U?
3.3V In-System Programmable SuperFAST High Density PLD
footprint PQFP160_N (QFP, 160-Leads, Body 28 x 28mm, Pitch 0.65mm, IPC Medium Density)
footprint PQFP160_L (QFP, 160-Leads, Body 28 x 28mm, Pitch 0.65mm, IPC High Density)
footprint PQFP160_M (QFP, 160-Leads, Body 28 x 28mm, Pitch 0.65mm, IPC Low Density)
3D model 2128VE-PQFP160 (160-Pin Quad Flat Pack 0.65 mm Pitch)
part A pins: 1 I/O113 (io), 3 I/O114 (io), 4 I/O115 (io), 5 I/O116 (io), 6 I/O117 (io), 7 I/O118 (io), 8 I/O119 (io), 9 I/O120 (io), 10 I/O121 (io), 11 I/O122 (io), 12 I/O123 (io), 13 I/O124 (io), 14 I/O125 (io), 15 I/O126 (io), 16 I/O127 (io), 17 IN7 (in), 18 Y0 (in), 19 ~{RESET} (in), 21 GOE1 (in), 23 ~{BSCA}N (in), 24 TDI/IN0 (in), 25 I/O0 (io), 26 I/O1 (io), 27 I/O2 (io), 28 I/O3 (io), 29 I/O4 (io), 30 I/O5 (io), 31 I/O6 (io), 32 I/O7 (io), 33 I/O8 (io), 34 I/O9 (io), 35 I/O10 (io), 36 I/O11 (io), 37 I/O12 (io), 38 I/O13 (io), 40 I/O14 (io), 41 I/O15 (io), 43 I/O16 (io), 44 I/O17 (io), 45 I/O18 (io), 46 I/O19 (io), 47 I/O20 (io), 48 I/O21 (io), 49 I/O22 (io), 50 I/O23 (io), 51 I/O24 (io), 52 I/O25 (io), 53 I/O26 (io), 54 I/O27 (io), 55 I/O28 (io), 56 I/O29 (io), 57 I/O30 (io), 58 I/O31 (io), 60 TMS/IN1 (in), 61 IN6 (in), 63 I/O32 (io), 64 I/O33 (io), 65 I/O34 (io), 66 I/O35 (io), 67 I/O36 (io), 68 I/O37 (io), 69 I/O38 (io), 70 I/O39 (io), 71 I/O40 (io), 72 I/O41 (io), 73 I/O42 (io), 74 I/O43 (io), 75 I/O44 (io), 76 I/O45 (io), 77 I/O46 (io), 78 I/O47 (io), 80 I/O48 (io), 81 I/O49 (io), 83 I/O50 (io), 84 I/O51 (io), 85 I/O52 (io), 86 I/O53 (io), 87 I/O54 (io), 88 I/O55 (io), 89 I/O56 (io), 90 I/O57 (io), 91 I/O58 (io), 92 I/O59 (io), 93 I/O60 (io), 94 I/O61 (io), 95 I/O62 (io), 96 I/O63 (io), 97 TCK/IN3 (in), 98 Y2 (in), 100 GOE0 (in), 103 Y1 (in), 104 IN4 (in), 105 I/O64 (io), 106 I/O65 (io), 107 I/O66 (io), 108 I/O67 (io), 109 I/O68 (io), 110 I/O69 (io), 111 I/O70 (io), 112 I/O71 (io), 113 I/O72 (io), 114 I/O73 (io), 115 I/O74 (io), 116 I/O75 (io), 117 I/O76 (io), 118 I/O77 (io), 120 I/O78 (io), 121 I/O79 (io), 123 I/O80 (io), 124 I/O81 (io), 125 I/O82 (io), 126 I/O83 (io), 127 I/O84 (io), 128 I/O85 (io), 129 I/O86 (io), 130 I/O87 (io), 131 I/O88 (io), 132 I/O89 (io), 133 I/O90 (io), 134 I/O91 (io), 135 I/O92 (io), 136 I/O93 (io), 137 I/O94 (io), 138 I/O95 (io), 140 TDO/IN2 (io), 141 IN5 (in), 143 I/O96 (io) hidden to I/O96, 144 I/O97 (io), 145 I/O98 (io), 146 I/O99 (io), 147 I/O100 (io), 148 I/O101 (io), 149 I/O102 (io), 150 I/O103 (io), 151 I/O104 (io), 152 I/O105 (io), 153 I/O106 (io), 154 I/O107 (io), 155 I/O108 (io), 156 I/O109 (io), 157 I/O110 (io), 158 I/O111 (io), 160 I/O112 (io)
part B pins: 2 VCC (power), 20 VCC (power), 22 GND (power), 39 VCC (power), 42 GND (power), 59 VCC (power), 62 GND (power), 79 GND (power), 82 VCC (power), 99 GND (power), 101 VCC (power), 102 NC, 119 VCC (power), 122 GND (power), 139 GND (power), 142 VCC (power), 159 GND (power)

## ispLSI2128VE-100LT100
designator U?
3.3V In-System Programmable SuperFAST High Density PLD
footprint TQFP100_N (Thin QFP, 100-Leads, Body 14x14mm, Pitch 0.5mm, IPC Medium Density)
footprint TQFP100_L (Thin QFP, 100-Leads, Body 14x14mm, Pitch 0.5mm, IPC High Density)
footprint TQFP100_M (Thin QFP, 100-Leads, Body 14x14mm, Pitch 0.5mm, IPC Low Density)
3D model 2128VE-TQFP100 (100-Pin Thin Quad Flat Pack (TQFP100))
pins: 1 I/O57 (io), 2 I/O58 (io), 3 I/O59 (io), 4 NC, 5 I/O60 (io), 6 I/O61 (io), 7 I/O62 (io), 8 I/O63 (io), 9 IN7 (in), 10 Y0 (in), 11 ~{RESET} (in), 12 VCC (power), 13 GOE1 (in), 14 GND (power), 15 ~{BSCAN} (in), 16 TDI/IN0 (in), 17 I/O0 (io), 18 I/O1 (io), 19 I/O2 (io), 20 I/O3 (io), 21 NC, 22 I/O4 (io), 23 I/O5 (io), 24 I/O6 (io), 25 NC, 26 I/O7 (io), 27 I/O8 (io), 28 I/O9 (io), 29 I/O10 (io), 30 I/O11 (io), 31 NC, 32 I/O12 (io), 33 I/O13 (io), 34 I/O14 (io), 35 I/O15 (io), 36 VCC (power), 37 TMS/IN1 (in), 38 IN6 (in), 39 GND (power), 40 I/O16 (io), 41 I/O17 (io), 42 I/O18 (io), 43 I/O19 (io), 44 NC, 45 I/O20 (io), 46 I/O21 (io), 47 I/O22 (io), 48 I/O23 (io), 49 I/O24 (io), 50 NC, 51 I/O25 (io), 52 I/O26 (io), 53 I/O27 (io), 54 NC, 55 I/O28 (io), 56 I/O29 (io), 57 I/O30 (io), 58 I/O31 (io), 59 TCK/IN3 (in), 60 Y2 (in), 61 GND (power), 62 GOE0 (in), 63 VCC (power), 64 NC, 65 Y1 (in), 66 IN4 (in), 67 I/O32 (io), 68 I/O33 (io), 69 I/O34 (io), 70 I/O35 (io), 71 NC, 72 I/O36 (io), 73 I/O37 (io), 74 I/O38 (io), 75 NC, 76 I/O39 (io), 77 I/O40 (io), 78 I/O41 (io), 79 I/O42 (io), 80 I/O43 (io), 81 NC, 82 I/O44 (io), 83 I/O45 (io), 84 I/O46 (io), 85 I/O47 (io), 86 GND (power), 87 TDO/IN2 (io), 88 IN5 (in), 89 VCC (power), 90 I/O48 (io), 91 I/O49 (io), 92 I/O50 (io), 93 I/O51 (io), 94 NC, 95 I/O52 (io), 96 I/O53 (io), 97 I/O54 (io), 98 I/O55 (io), 99 I/O56 (io), 100 NC

## ispLSI2128VE-100LT176
designator U?
3.3V In-System Programmable SuperFAST High Density PLD
footprint TQFP176_N (Thin QFP, 176-Leads, Body 24x24mm, Pitch 0.5mm, IPC Medium Density)
footprint TQFP176_L (Thin QFP, 176-Leads, Body 24x24mm, Pitch 0.5mm, IPC High Density)
footprint TQFP176_M (Thin QFP, 176-Leads, Body 24x24mm, Pitch 0.5mm, IPC Low Density)
3D model 2128VE-TQFP176 (176-Pin Thin Quad Flat Pack 0.5 mm Pitch)
part A pins: 1 I/O113 (io), 3 I/O114 (io), 4 I/O115 (io), 5 I/O116 (io), 6 I/O117 (io), 7 I/O118 (io), 8 I/O119 (io), 10 I/O120 (io), 11 I/O121 (io), 12 I/O122 (io), 13 I/O123 (io), 14 I/O124 (io), 15 I/O125 (io), 16 I/O126 (io), 17 I/O127 (io), 19 IN7 (in), 20 Y0 (in), 21 ~{RESET} (in), 23 GOE1 (in), 25 ~{BSCAN} (in), 26 TDI/IN0 (in), 28 I/O0 (io), 29 I/O1 (io), 30 I/O2 (io), 31 I/O3 (io), 32 I/O4 (io), 33 I/O5 (io), 34 I/O6 (io), 35 I/O7 (io), 37 I/O8 (io), 38 I/O9 (io), 39 I/O10 (io), 40 I/O11 (io), 41 I/O12 (io), 42 I/O13 (io), 44 I/O14 (io), 45 I/O15 (io), 47 I/O16 (io), 48 I/O17 (io), 49 I/O18 (io), 50 I/O19 (io), 51 I/O20 (io), 52 I/O21 (io), 53 I/O22 (io), 54 I/O23 (io), 56 I/O24 (io), 57 I/O25 (io), 58 I/O26 (io), 59 I/O27 (io), 60 I/O28 (io), 61 I/O29 (io), 62 I/O30 (io), 63 I/O31 (io), 66 TMS/IN1 (in), 67 IN6 (in), 70 I/O32 (io), 71 I/O33 (io), 72 I/O34 (io), 73 I/O35 (io), 74 I/O36 (io), 75 I/O37 (io), 76 I/O38 (io), 77 I/O39 (io), 79 I/O40 (io), 80 I/O41 (io), 81 I/O42 (io), 82 I/O43 (io), 83 I/O44 (io), 84 I/O45 (io), 85 I/O46 (io), 86 I/O47 (io), 88 I/O48 (io), 89 I/O49 (io), 91 I/O50 (io), 92 I/O51 (io), 93 I/O52 (io), 94 I/O53 (io), 95 I/O54 (io), 96 I/O55 (io), 98 I/O56 (io), 99 I/O57 (io), 100 I/O58 (io), 101 I/O59 (io), 102 I/O60 (io), 103 I/O61 (io), 104 I/O62 (io), 105 I/O63 (io), 107 TCK/IN3 (in), 108 Y2 (in), 110 GOE0 (in), 113 Y1 (in), 114 IN4 (in), 116 I/O64 (io), 117 I/O65 (io), 118 I/O66 (io), 119 I/O67 (io), 120 I/O68 (io), 121 I/O69 (io), 122 I/O70 (io), 123 I/O71 (io), 125 I/O72 (io), 126 I/O73 (io), 127 I/O74 (io), 128 I/O75 (io), 129 I/O76 (io), 130 I/O77 (io), 132 I/O78 (io), 133 I/O79 (io), 135 I/O80 (io), 136 I/O81 (io), 137 I/O82 (io), 138 I/O83 (io), 139 I/O84 (io), 140 I/O85 (io), 141 I/O86 (io), 142 I/O87 (io), 144 I/O88 (io), 145 I/O89 (io), 146 I/O90 (io), 147 I/O91 (io), 148 I/O92 (io), 149 I/O93 (io), 150 I/O94 (io), 151 I/O95 (io), 154 TDO/IN2 (io), 155 IN5 (in), 158 I/O96 (io), 159 I/O97 (io), 160 I/O98 (io), 161 I/O99 (io), 162 I/O100 (io), 163 I/O101 (io), 164 I/O102 (io), 165 I/O103 (io), 167 I/O104 (io), 168 I/O105 (io), 169 I/O106 (io), 170 I/O107 (io), 171 I/O108 (io), 172 I/O109 (io), 173 I/O110 (io), 174 I/O111 (io), 176 I/O112 (io)
part B pins: 2 VCC (power), 9 NC, 18 NC, 22 VCC (power), 24 GND (power), 27 NC, 36 NC, 43 VCC (power), 46 GND (power), 55 NC, 64 NC, 65 VCC (power), 68 GND (power), 69 NC, 78 NC, 87 GND (power), 90 VCC (power), 97 NC, 106 NC, 109 GND (power), 111 VCC (power), 112 NC, 115 NC, 124 NC, 131 VCC (power), 134 GND (power), 143 NC, 152 NC, 153 GND (power), 156 VCC (power), 157 NC, 166 NC, 175 GND (power)

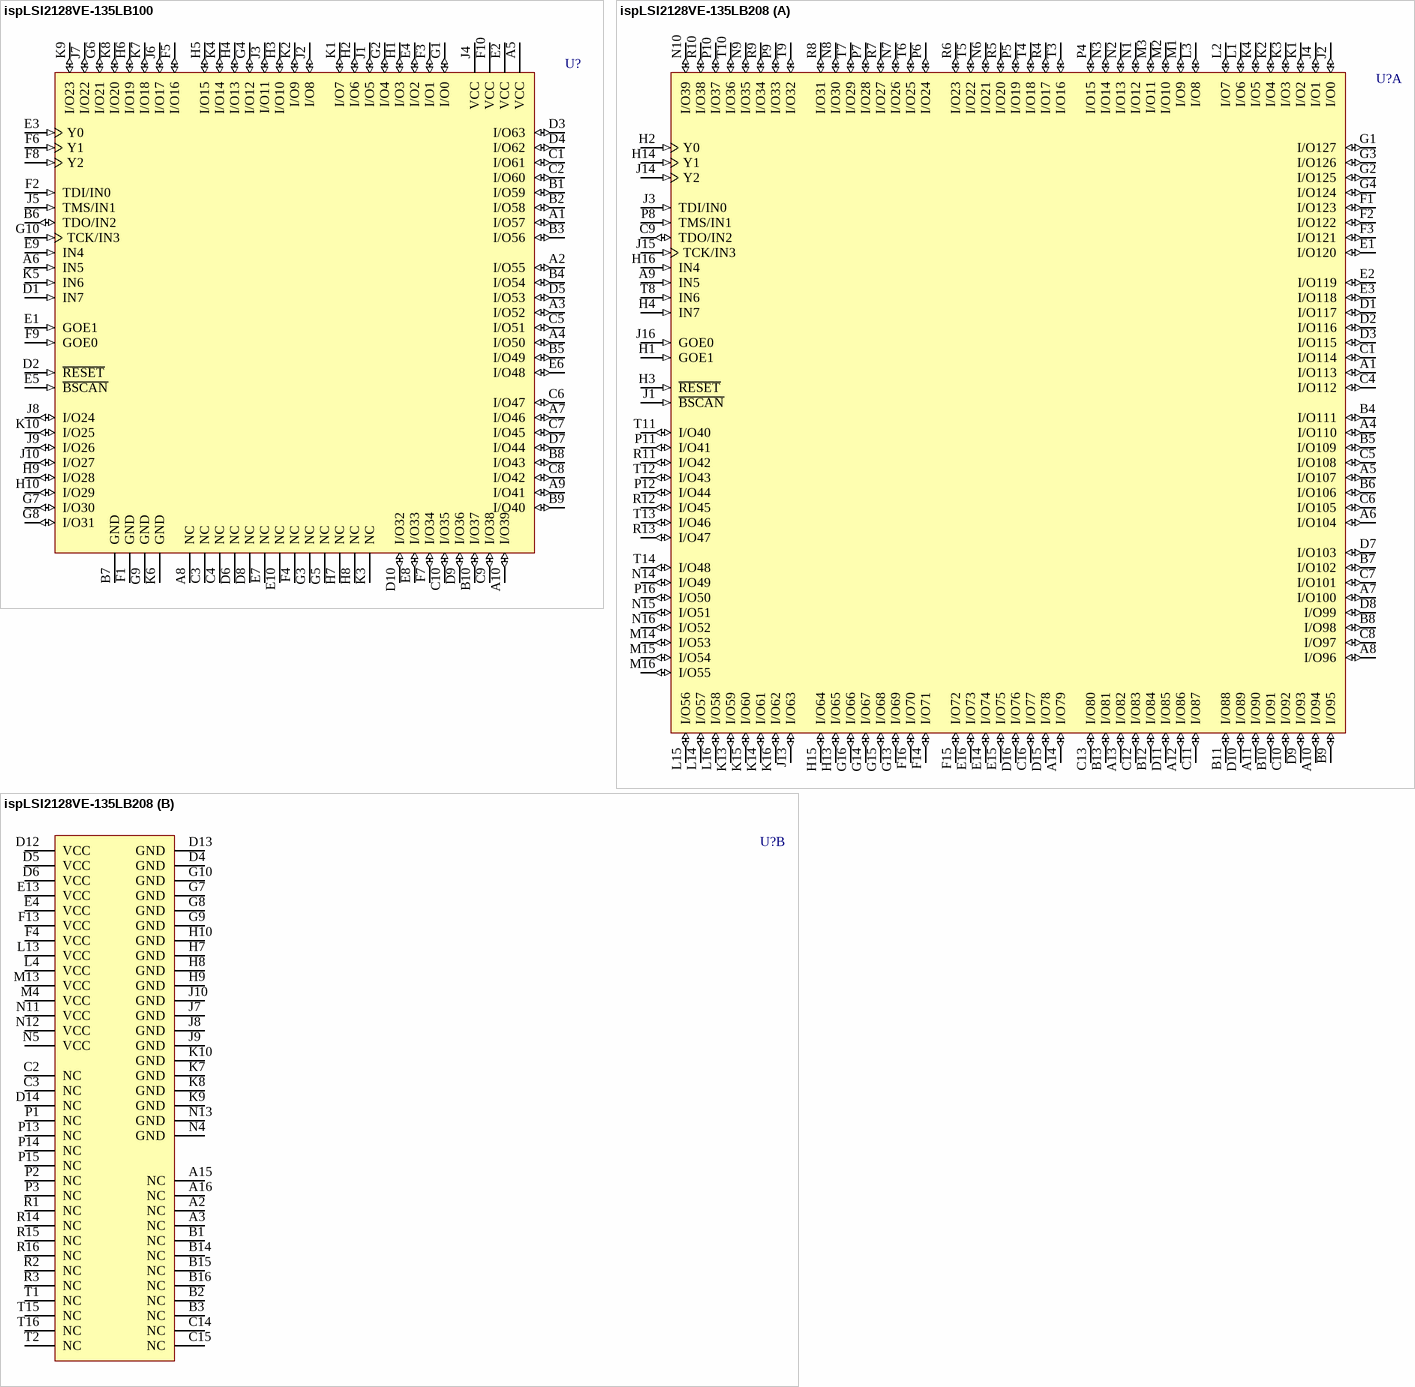
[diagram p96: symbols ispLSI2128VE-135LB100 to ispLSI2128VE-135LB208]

## ispLSI2128VE-135LB100
designator U?
3.3V In-System Programmable SuperFAST High Density PLD
footprint caBGA100 (BGA, 100-Leads, Body 10x10mm, Pitch 0.8mm)
3D model 2128VE-caBGA100 (100-Ball Chip Array Ball Grid Array (caBGA100))
pins: A1 I/O57 (io), A2 I/O55 (io), A3 I/O52 (io), A4 I/O50 (io), A5 VCC (power), A6 IN5 (in), A7 I/O46 (io), A8 NC, A9 I/O41 (io), A10 I/O39 (io), B1 I/O59 (io), B2 I/O58 (io), B3 I/O56 (io), B4 I/O54 (io), B5 I/O49 (io), B6 TDO/IN2 (io), B7 GND (power), B8 I/O43 (io), B9 I/O40 (io), B10 I/O37 (io), C1 I/O61 (io), C2 I/O60 (io), C3 NC, C4 NC, C5 I/O51 (io), C6 I/O47 (io), C7 I/O45 (io), C8 I/O42 (io), C9 I/O38 (io), C10 I/O35 (io), D1 IN7 (in), D2 ~{RESET} (in), D3 I/O63 (io), D4 I/O62 (io), D5 I/O53 (io), D6 NC, D7 I/O44 (io), D8 NC, D9 I/O36 (io), D10 I/O32 (io), E1 GOE1 (in), E2 VCC (power), E3 Y0 (in), E4 I/O2 (io), E5 ~{BSCAN} (in), E6 I/O48 (io), E7 NC, E8 I/O33 (io), E9 IN4 (in), E10 NC, F1 GND (power), F2 TDI/IN0 (in), F3 I/O1 (io), F4 NC, F5 I/O16 (io), F6 Y1 (in), F7 I/O34 (io), F8 Y2 (in), F9 GOE0 (in), F10 VCC (power), G1 I/O0 (io), G2 I/O4 (io), G3 NC, G4 I/O12 (io), G5 NC, G6 I/O21 (io), G7 I/O30 (io), G8 I/O31 (io), G9 GND (power), G10 TCK/IN3 (in), H1 I/O3 (io), H2 I/O6 (io), H3 I/O10 (io), H4 I/O13 (io), H5 I/O15 (io), H6 I/O19 (io), H7 NC, H8 NC, H9 I/O28 (io), H10 I/O29 (io), J1 I/O5 (io), J2 I/O8 (io), J3 I/O11 (io), J4 VCC (power), J5 TMS/IN1 (in), J6 I/O17 (io), J7 I/O22 (io), J8 I/O24 (io), J9 I/O26 (io), J10 I/O27 (io), K1 I/O7 (io), K2 I/O9 (io), K3 NC, K4 I/O14 (io), K5 IN6 (in), K6 GND (power), K7 I/O18 (io), K8 I/O20 (io), K9 I/O23 (io), K10 I/O25 (io)

## ispLSI2128VE-135LB208
designator U?
3.3V In-System Programmable SuperFAST High Density PLD
footprint fpBGA208 (BGA, 208-Leads, Body 17x17mm, Pitch 1mm)
3D model 2128VE-fpBGA208 (208-Ball Fine Pitch Ball Grid Array (fpBGA208))
part A pins: A1 I/O113 (io), A4 I/O110 (io), A5 I/O107 (io), A6 I/O104 (io), A7 I/O100 (io), A8 I/O96 (io), A9 IN5 (in), A10 I/O94 (io), A11 I/O90 (io), A12 I/O86 (io), A13 I/O82 (io), A14 I/O79 (io), B4 I/O111 (io), B5 I/O109 (io), B6 I/O106 (io), B7 I/O102 (io), B8 I/O98 (io), B9 I/O95 (io), B10 I/O91 (io), B11 I/O88 (io), B12 I/O84 (io), B13 I/O81 (io), C1 I/O114 (io), C4 I/O112 (io), C5 I/O108 (io), C6 I/O105 (io), C7 I/O101 (io), C8 I/O97 (io), C9 TDO/IN2 (io), C10 I/O92 (io), C11 I/O87 (io), C12 I/O83 (io), C13 I/O80 (io), C16 I/O77 (io), D1 I/O117 (io), D2 I/O116 (io), D3 I/O115 (io), D7 I/O103 (io), D8 I/O99 (io), D9 I/O93 (io), D10 I/O89 (io), D11 I/O85 (io), D15 I/O78 (io), D16 I/O76 (io), E1 I/O120 (io), E2 I/O119 (io), E3 I/O118 (io), E14 I/O74 (io), E15 I/O75 (io), E16 I/O73 (io), F1 I/O123 (io), F2 I/O122 (io), F3 I/O121 (io), F14 I/O71 (io), F15 I/O72 (io), F16 I/O70 (io), G1 I/O127 (io), G2 I/O125 (io), G3 I/O126 (io), G4 I/O124 (io), G13 I/O69 (io), G14 I/O67 (io), G15 I/O68 (io), G16 I/O66 (io), H1 GOE1 (in), H2 Y0 (in), H3 ~{RESET} (in), H4 IN7 (in), H13 I/O65 (io), H14 Y1 (in), H15 I/O64 (io), H16 IN4 (in), J1 ~{BSCAN} (in), J2 I/O0 (io), J3 TDI/IN0 (in), J4 I/O1 (io), J13 I/O63 (io), J14 Y2 (in), J15 TCK/IN3 (in), J16 GOE0 (in), K1 I/O2 (io), K2 I/O4 (io), K3 I/O3 (io), K4 I/O5 (io), K13 I/O59 (io), K14 I/O61 (io), K15 I/O60 (io), K16 I/O62 (io), L1 I/O6 (io), L2 I/O7 (io), L3 I/O8 (io), L14 I/O57 (io), L15 I/O56 (io), L16 I/O58 (io), M1 I/O9 (io), M2 I/O10 (io), M3 I/O11 (io), M14 I/O53 (io), M15 I/O54 (io), M16 I/O55 (io), N1 I/O12 (io), N2 I/O13 (io), N3 I/O14 (io), N6 I/O21 (io), N7 I/O26 (io), N8 I/O30 (io), N9 I/O35 (io), N10 I/O39 (io), N14 I/O49 (io), N15 I/O51 (io), N16 I/O52 (io), P4 I/O15 (io), P5 I/O19 (io), P6 I/O24 (io), P7 I/O28 (io), P8 TMS/IN1 (in), P9 I/O33 (io), P10 I/O37 (io), P11 I/O41 (io), P12 I/O44 (io), P16 I/O50 (io), R4 I/O17 (io), R5 I/O20 (io), R6 I/O23 (io), R7 I/O27 (io), R8 I/O31 (io), R9 I/O34 (io), R10 I/O38 (io), R11 I/O42 (io), R12 I/O45 (io), R13 I/O47 (io), T3 I/O16 (io), T4 I/O18 (io), T5 I/O22 (io), T6 I/O25 (io), T7 I/O29 (io), T8 IN6 (in), T9 I/O32 (io), T10 I/O36 (io), T11 I/O40 (io), T12 I/O43 (io), T13 I/O46 (io), T14 I/O48 (io)
part B pins: A2 NC, A3 NC, A15 NC, A16 NC, B1 NC, B2 NC, B3 NC, B14 NC, B15 NC, B16 NC, C2 NC, C3 NC, C14 NC, C15 NC, D4 GND (power), D5 VCC (power), D6 VCC (power), D12 VCC (power), D13 GND (power), D14 NC, E4 VCC (power), E13 VCC (power), F4 VCC (power), F13 VCC (power), G7 GND (power), G8 GND (power), G9 GND (power), G10 GND (power), H7 GND (power), H8 GND (power), H9 GND (power), H10 GND (power), J7 GND (power), J8 GND (power), J9 GND (power), J10 GND (power), K7 GND (power), K8 GND (power), K9 GND (power), K10 GND (power), L4 VCC (power), L13 VCC (power), M4 VCC (power), M13 VCC (power), N4 GND (power), N5 VCC (power), N11 VCC (power), N12 VCC (power), N13 GND (power), P1 NC, P2 NC, P3 NC, P13 NC, P14 NC, P15 NC, R1 NC, R2 NC, R3 NC, R14 NC, R15 NC, R16 NC, T1 NC, T2 NC, T15 NC, T16 NC

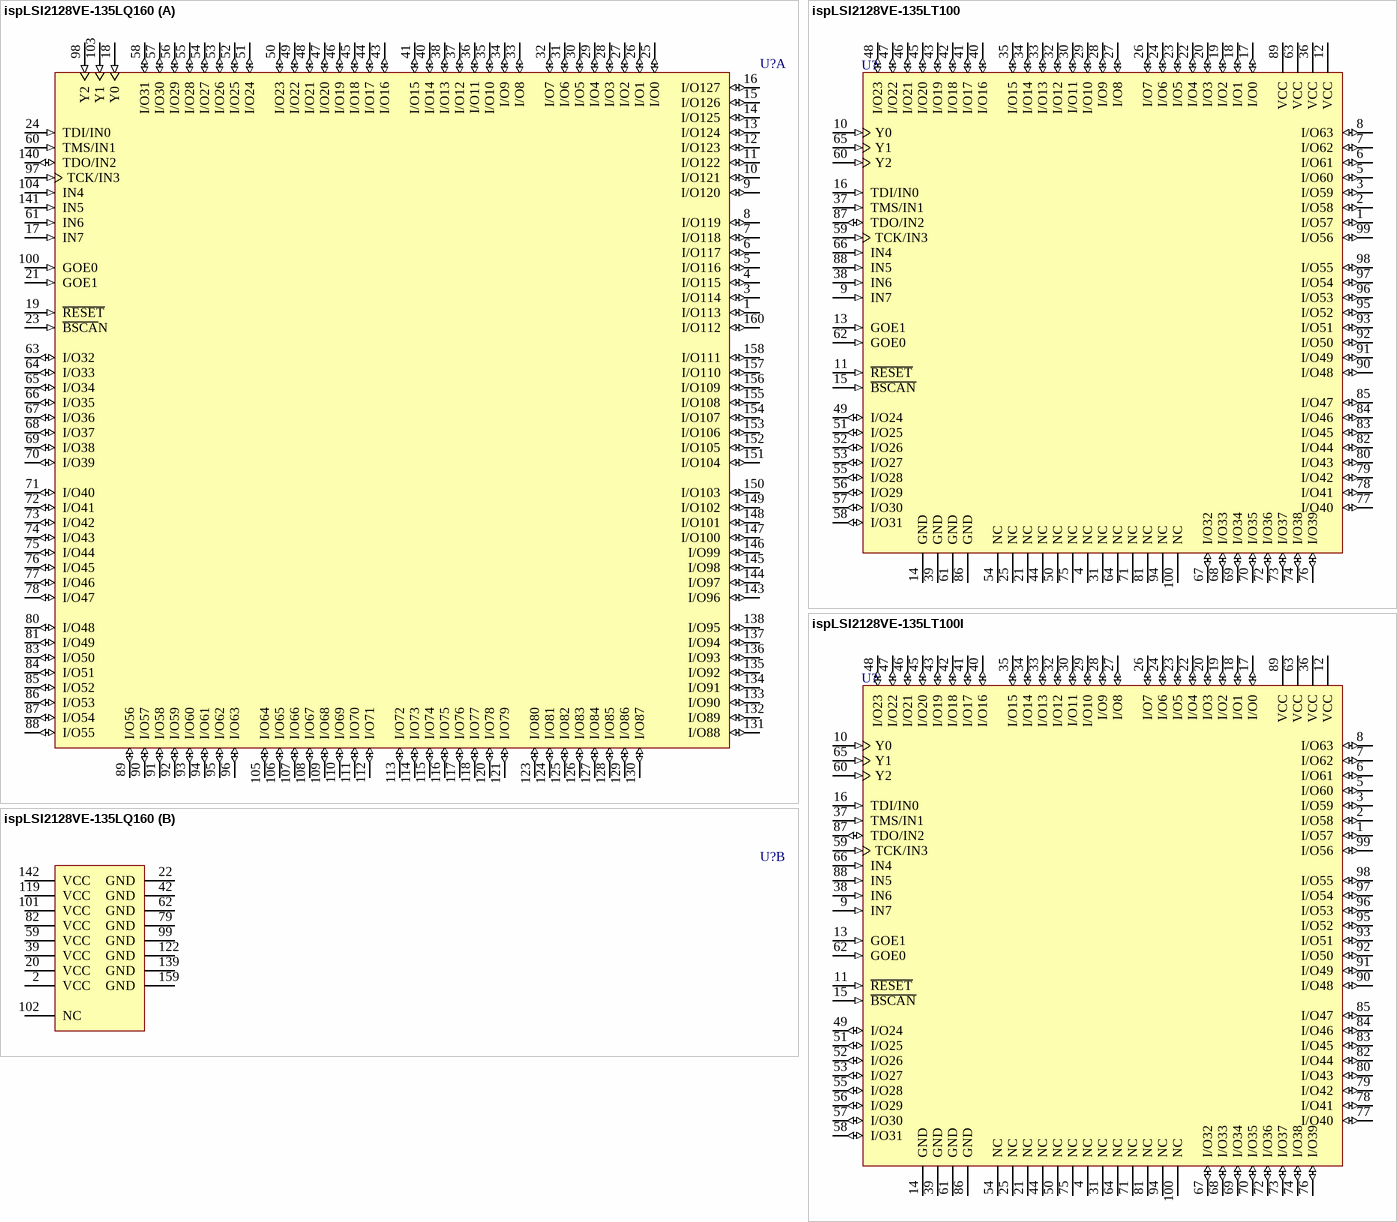
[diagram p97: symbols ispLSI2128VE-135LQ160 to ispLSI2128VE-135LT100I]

## ispLSI2128VE-135LQ160
designator U?
3.3V In-System Programmable SuperFAST High Density PLD
footprint PQFP160_N (QFP, 160-Leads, Body 28 x 28mm, Pitch 0.65mm, IPC Medium Density)
footprint PQFP160_L (QFP, 160-Leads, Body 28 x 28mm, Pitch 0.65mm, IPC High Density)
footprint PQFP160_M (QFP, 160-Leads, Body 28 x 28mm, Pitch 0.65mm, IPC Low Density)
3D model 2128VE-PQFP160 (160-Pin Quad Flat Pack 0.65 mm Pitch)
part A pins: 1 I/O113 (io), 3 I/O114 (io), 4 I/O115 (io), 5 I/O116 (io), 6 I/O117 (io), 7 I/O118 (io), 8 I/O119 (io), 9 I/O120 (io), 10 I/O121 (io), 11 I/O122 (io), 12 I/O123 (io), 13 I/O124 (io), 14 I/O125 (io), 15 I/O126 (io), 16 I/O127 (io), 17 IN7 (in), 18 Y0 (in), 19 ~{RESET} (in), 21 GOE1 (in), 23 ~{BSCA}N (in), 24 TDI/IN0 (in), 25 I/O0 (io), 26 I/O1 (io), 27 I/O2 (io), 28 I/O3 (io), 29 I/O4 (io), 30 I/O5 (io), 31 I/O6 (io), 32 I/O7 (io), 33 I/O8 (io), 34 I/O9 (io), 35 I/O10 (io), 36 I/O11 (io), 37 I/O12 (io), 38 I/O13 (io), 40 I/O14 (io), 41 I/O15 (io), 43 I/O16 (io), 44 I/O17 (io), 45 I/O18 (io), 46 I/O19 (io), 47 I/O20 (io), 48 I/O21 (io), 49 I/O22 (io), 50 I/O23 (io), 51 I/O24 (io), 52 I/O25 (io), 53 I/O26 (io), 54 I/O27 (io), 55 I/O28 (io), 56 I/O29 (io), 57 I/O30 (io), 58 I/O31 (io), 60 TMS/IN1 (in), 61 IN6 (in), 63 I/O32 (io), 64 I/O33 (io), 65 I/O34 (io), 66 I/O35 (io), 67 I/O36 (io), 68 I/O37 (io), 69 I/O38 (io), 70 I/O39 (io), 71 I/O40 (io), 72 I/O41 (io), 73 I/O42 (io), 74 I/O43 (io), 75 I/O44 (io), 76 I/O45 (io), 77 I/O46 (io), 78 I/O47 (io), 80 I/O48 (io), 81 I/O49 (io), 83 I/O50 (io), 84 I/O51 (io), 85 I/O52 (io), 86 I/O53 (io), 87 I/O54 (io), 88 I/O55 (io), 89 I/O56 (io), 90 I/O57 (io), 91 I/O58 (io), 92 I/O59 (io), 93 I/O60 (io), 94 I/O61 (io), 95 I/O62 (io), 96 I/O63 (io), 97 TCK/IN3 (in), 98 Y2 (in), 100 GOE0 (in), 103 Y1 (in), 104 IN4 (in), 105 I/O64 (io), 106 I/O65 (io), 107 I/O66 (io), 108 I/O67 (io), 109 I/O68 (io), 110 I/O69 (io), 111 I/O70 (io), 112 I/O71 (io), 113 I/O72 (io), 114 I/O73 (io), 115 I/O74 (io), 116 I/O75 (io), 117 I/O76 (io), 118 I/O77 (io), 120 I/O78 (io), 121 I/O79 (io), 123 I/O80 (io), 124 I/O81 (io), 125 I/O82 (io), 126 I/O83 (io), 127 I/O84 (io), 128 I/O85 (io), 129 I/O86 (io), 130 I/O87 (io), 131 I/O88 (io), 132 I/O89 (io), 133 I/O90 (io), 134 I/O91 (io), 135 I/O92 (io), 136 I/O93 (io), 137 I/O94 (io), 138 I/O95 (io), 140 TDO/IN2 (io), 141 IN5 (in), 143 I/O96 (io) hidden to I/O96, 144 I/O97 (io), 145 I/O98 (io), 146 I/O99 (io), 147 I/O100 (io), 148 I/O101 (io), 149 I/O102 (io), 150 I/O103 (io), 151 I/O104 (io), 152 I/O105 (io), 153 I/O106 (io), 154 I/O107 (io), 155 I/O108 (io), 156 I/O109 (io), 157 I/O110 (io), 158 I/O111 (io), 160 I/O112 (io)
part B pins: 2 VCC (power), 20 VCC (power), 22 GND (power), 39 VCC (power), 42 GND (power), 59 VCC (power), 62 GND (power), 79 GND (power), 82 VCC (power), 99 GND (power), 101 VCC (power), 102 NC, 119 VCC (power), 122 GND (power), 139 GND (power), 142 VCC (power), 159 GND (power)

## ispLSI2128VE-135LT100
designator U?
3.3V In-System Programmable SuperFAST High Density PLD
footprint TQFP100_N (Thin QFP, 100-Leads, Body 14x14mm, Pitch 0.5mm, IPC Medium Density)
footprint TQFP100_L (Thin QFP, 100-Leads, Body 14x14mm, Pitch 0.5mm, IPC High Density)
footprint TQFP100_M (Thin QFP, 100-Leads, Body 14x14mm, Pitch 0.5mm, IPC Low Density)
3D model 2128VE-TQFP100 (100-Pin Thin Quad Flat Pack (TQFP100))
pins: 1 I/O57 (io), 2 I/O58 (io), 3 I/O59 (io), 4 NC, 5 I/O60 (io), 6 I/O61 (io), 7 I/O62 (io), 8 I/O63 (io), 9 IN7 (in), 10 Y0 (in), 11 ~{RESET} (in), 12 VCC (power), 13 GOE1 (in), 14 GND (power), 15 ~{BSCAN} (in), 16 TDI/IN0 (in), 17 I/O0 (io), 18 I/O1 (io), 19 I/O2 (io), 20 I/O3 (io), 21 NC, 22 I/O4 (io), 23 I/O5 (io), 24 I/O6 (io), 25 NC, 26 I/O7 (io), 27 I/O8 (io), 28 I/O9 (io), 29 I/O10 (io), 30 I/O11 (io), 31 NC, 32 I/O12 (io), 33 I/O13 (io), 34 I/O14 (io), 35 I/O15 (io), 36 VCC (power), 37 TMS/IN1 (in), 38 IN6 (in), 39 GND (power), 40 I/O16 (io), 41 I/O17 (io), 42 I/O18 (io), 43 I/O19 (io), 44 NC, 45 I/O20 (io), 46 I/O21 (io), 47 I/O22 (io), 48 I/O23 (io), 49 I/O24 (io), 50 NC, 51 I/O25 (io), 52 I/O26 (io), 53 I/O27 (io), 54 NC, 55 I/O28 (io), 56 I/O29 (io), 57 I/O30 (io), 58 I/O31 (io), 59 TCK/IN3 (in), 60 Y2 (in), 61 GND (power), 62 GOE0 (in), 63 VCC (power), 64 NC, 65 Y1 (in), 66 IN4 (in), 67 I/O32 (io), 68 I/O33 (io), 69 I/O34 (io), 70 I/O35 (io), 71 NC, 72 I/O36 (io), 73 I/O37 (io), 74 I/O38 (io), 75 NC, 76 I/O39 (io), 77 I/O40 (io), 78 I/O41 (io), 79 I/O42 (io), 80 I/O43 (io), 81 NC, 82 I/O44 (io), 83 I/O45 (io), 84 I/O46 (io), 85 I/O47 (io), 86 GND (power), 87 TDO/IN2 (io), 88 IN5 (in), 89 VCC (power), 90 I/O48 (io), 91 I/O49 (io), 92 I/O50 (io), 93 I/O51 (io), 94 NC, 95 I/O52 (io), 96 I/O53 (io), 97 I/O54 (io), 98 I/O55 (io), 99 I/O56 (io), 100 NC

## ispLSI2128VE-135LT100I
designator U?
3.3V In-System Programmable SuperFAST High Density PLD
footprint TQFP100_N (Thin QFP, 100-Leads, Body 14x14mm, Pitch 0.5mm, IPC Medium Density)
footprint TQFP100_L (Thin QFP, 100-Leads, Body 14x14mm, Pitch 0.5mm, IPC High Density)
footprint TQFP100_M (Thin QFP, 100-Leads, Body 14x14mm, Pitch 0.5mm, IPC Low Density)
3D model 2128VE-TQFP100 (100-Pin Thin Quad Flat Pack (TQFP100))
pins: 1 I/O57 (io), 2 I/O58 (io), 3 I/O59 (io), 4 NC, 5 I/O60 (io), 6 I/O61 (io), 7 I/O62 (io), 8 I/O63 (io), 9 IN7 (in), 10 Y0 (in), 11 ~{RESET} (in), 12 VCC (power), 13 GOE1 (in), 14 GND (power), 15 ~{BSCAN} (in), 16 TDI/IN0 (in), 17 I/O0 (io), 18 I/O1 (io), 19 I/O2 (io), 20 I/O3 (io), 21 NC, 22 I/O4 (io), 23 I/O5 (io), 24 I/O6 (io), 25 NC, 26 I/O7 (io), 27 I/O8 (io), 28 I/O9 (io), 29 I/O10 (io), 30 I/O11 (io), 31 NC, 32 I/O12 (io), 33 I/O13 (io), 34 I/O14 (io), 35 I/O15 (io), 36 VCC (power), 37 TMS/IN1 (in), 38 IN6 (in), 39 GND (power), 40 I/O16 (io), 41 I/O17 (io), 42 I/O18 (io), 43 I/O19 (io), 44 NC, 45 I/O20 (io), 46 I/O21 (io), 47 I/O22 (io), 48 I/O23 (io), 49 I/O24 (io), 50 NC, 51 I/O25 (io), 52 I/O26 (io), 53 I/O27 (io), 54 NC, 55 I/O28 (io), 56 I/O29 (io), 57 I/O30 (io), 58 I/O31 (io), 59 TCK/IN3 (in), 60 Y2 (in), 61 GND (power), 62 GOE0 (in), 63 VCC (power), 64 NC, 65 Y1 (in), 66 IN4 (in), 67 I/O32 (io), 68 I/O33 (io), 69 I/O34 (io), 70 I/O35 (io), 71 NC, 72 I/O36 (io), 73 I/O37 (io), 74 I/O38 (io), 75 NC, 76 I/O39 (io), 77 I/O40 (io), 78 I/O41 (io), 79 I/O42 (io), 80 I/O43 (io), 81 NC, 82 I/O44 (io), 83 I/O45 (io), 84 I/O46 (io), 85 I/O47 (io), 86 GND (power), 87 TDO/IN2 (io), 88 IN5 (in), 89 VCC (power), 90 I/O48 (io), 91 I/O49 (io), 92 I/O50 (io), 93 I/O51 (io), 94 NC, 95 I/O52 (io), 96 I/O53 (io), 97 I/O54 (io), 98 I/O55 (io), 99 I/O56 (io), 100 NC

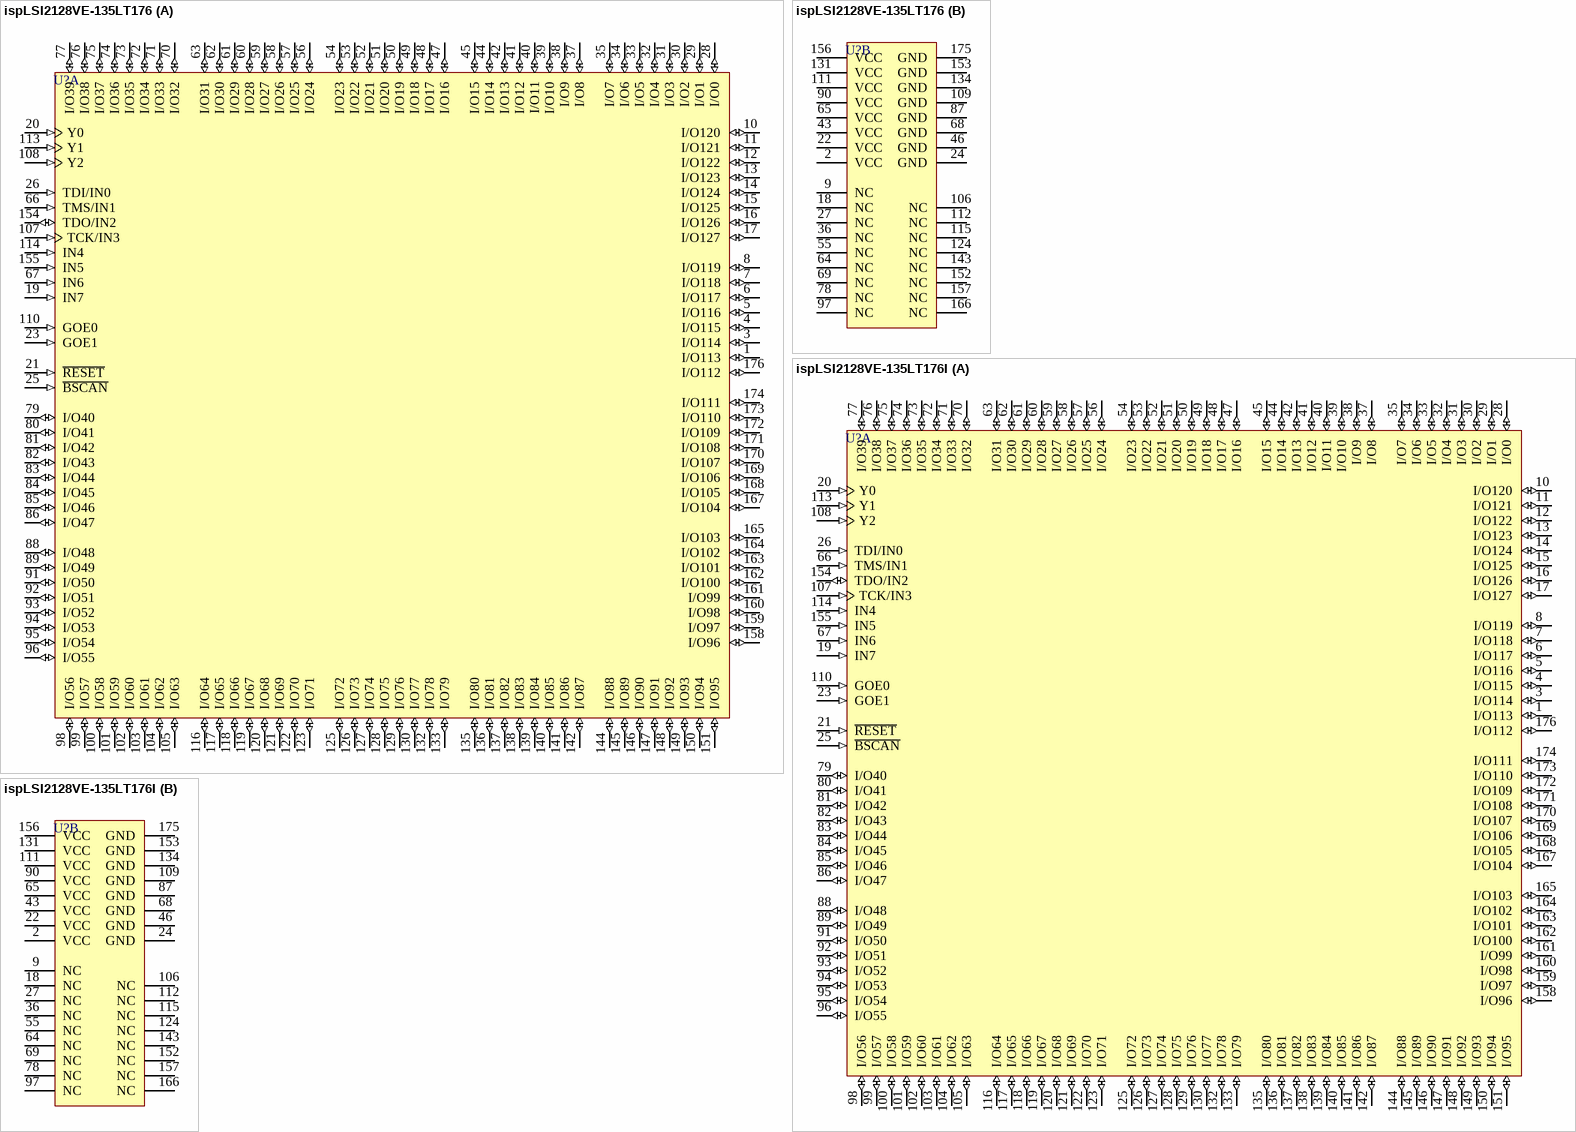
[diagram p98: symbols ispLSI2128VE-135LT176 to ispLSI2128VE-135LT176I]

## ispLSI2128VE-135LT176
designator U?
3.3V In-System Programmable SuperFAST High Density PLD
footprint TQFP176_N (Thin QFP, 176-Leads, Body 24x24mm, Pitch 0.5mm, IPC Medium Density)
footprint TQFP176_L (Thin QFP, 176-Leads, Body 24x24mm, Pitch 0.5mm, IPC High Density)
footprint TQFP176_M (Thin QFP, 176-Leads, Body 24x24mm, Pitch 0.5mm, IPC Low Density)
3D model 2128VE-TQFP176 (176-Pin Thin Quad Flat Pack 0.5 mm Pitch)
part A pins: 1 I/O113 (io), 3 I/O114 (io), 4 I/O115 (io), 5 I/O116 (io), 6 I/O117 (io), 7 I/O118 (io), 8 I/O119 (io), 10 I/O120 (io), 11 I/O121 (io), 12 I/O122 (io), 13 I/O123 (io), 14 I/O124 (io), 15 I/O125 (io), 16 I/O126 (io), 17 I/O127 (io), 19 IN7 (in), 20 Y0 (in), 21 ~{RESET} (in), 23 GOE1 (in), 25 ~{BSCAN} (in), 26 TDI/IN0 (in), 28 I/O0 (io), 29 I/O1 (io), 30 I/O2 (io), 31 I/O3 (io), 32 I/O4 (io), 33 I/O5 (io), 34 I/O6 (io), 35 I/O7 (io), 37 I/O8 (io), 38 I/O9 (io), 39 I/O10 (io), 40 I/O11 (io), 41 I/O12 (io), 42 I/O13 (io), 44 I/O14 (io), 45 I/O15 (io), 47 I/O16 (io), 48 I/O17 (io), 49 I/O18 (io), 50 I/O19 (io), 51 I/O20 (io), 52 I/O21 (io), 53 I/O22 (io), 54 I/O23 (io), 56 I/O24 (io), 57 I/O25 (io), 58 I/O26 (io), 59 I/O27 (io), 60 I/O28 (io), 61 I/O29 (io), 62 I/O30 (io), 63 I/O31 (io), 66 TMS/IN1 (in), 67 IN6 (in), 70 I/O32 (io), 71 I/O33 (io), 72 I/O34 (io), 73 I/O35 (io), 74 I/O36 (io), 75 I/O37 (io), 76 I/O38 (io), 77 I/O39 (io), 79 I/O40 (io), 80 I/O41 (io), 81 I/O42 (io), 82 I/O43 (io), 83 I/O44 (io), 84 I/O45 (io), 85 I/O46 (io), 86 I/O47 (io), 88 I/O48 (io), 89 I/O49 (io), 91 I/O50 (io), 92 I/O51 (io), 93 I/O52 (io), 94 I/O53 (io), 95 I/O54 (io), 96 I/O55 (io), 98 I/O56 (io), 99 I/O57 (io), 100 I/O58 (io), 101 I/O59 (io), 102 I/O60 (io), 103 I/O61 (io), 104 I/O62 (io), 105 I/O63 (io), 107 TCK/IN3 (in), 108 Y2 (in), 110 GOE0 (in), 113 Y1 (in), 114 IN4 (in), 116 I/O64 (io), 117 I/O65 (io), 118 I/O66 (io), 119 I/O67 (io), 120 I/O68 (io), 121 I/O69 (io), 122 I/O70 (io), 123 I/O71 (io), 125 I/O72 (io), 126 I/O73 (io), 127 I/O74 (io), 128 I/O75 (io), 129 I/O76 (io), 130 I/O77 (io), 132 I/O78 (io), 133 I/O79 (io), 135 I/O80 (io), 136 I/O81 (io), 137 I/O82 (io), 138 I/O83 (io), 139 I/O84 (io), 140 I/O85 (io), 141 I/O86 (io), 142 I/O87 (io), 144 I/O88 (io), 145 I/O89 (io), 146 I/O90 (io), 147 I/O91 (io), 148 I/O92 (io), 149 I/O93 (io), 150 I/O94 (io), 151 I/O95 (io), 154 TDO/IN2 (io), 155 IN5 (in), 158 I/O96 (io), 159 I/O97 (io), 160 I/O98 (io), 161 I/O99 (io), 162 I/O100 (io), 163 I/O101 (io), 164 I/O102 (io), 165 I/O103 (io), 167 I/O104 (io), 168 I/O105 (io), 169 I/O106 (io), 170 I/O107 (io), 171 I/O108 (io), 172 I/O109 (io), 173 I/O110 (io), 174 I/O111 (io), 176 I/O112 (io)
part B pins: 2 VCC (power), 9 NC, 18 NC, 22 VCC (power), 24 GND (power), 27 NC, 36 NC, 43 VCC (power), 46 GND (power), 55 NC, 64 NC, 65 VCC (power), 68 GND (power), 69 NC, 78 NC, 87 GND (power), 90 VCC (power), 97 NC, 106 NC, 109 GND (power), 111 VCC (power), 112 NC, 115 NC, 124 NC, 131 VCC (power), 134 GND (power), 143 NC, 152 NC, 153 GND (power), 156 VCC (power), 157 NC, 166 NC, 175 GND (power)

## ispLSI2128VE-135LT176I
designator U?
3.3V In-System Programmable SuperFAST High Density PLD
footprint TQFP176_N (Thin QFP, 176-Leads, Body 24x24mm, Pitch 0.5mm, IPC Medium Density)
footprint TQFP176_L (Thin QFP, 176-Leads, Body 24x24mm, Pitch 0.5mm, IPC High Density)
footprint TQFP176_M (Thin QFP, 176-Leads, Body 24x24mm, Pitch 0.5mm, IPC Low Density)
3D model 2128VE-TQFP176 (176-Pin Thin Quad Flat Pack 0.5 mm Pitch)
part A pins: 1 I/O113 (io), 3 I/O114 (io), 4 I/O115 (io), 5 I/O116 (io), 6 I/O117 (io), 7 I/O118 (io), 8 I/O119 (io), 10 I/O120 (io), 11 I/O121 (io), 12 I/O122 (io), 13 I/O123 (io), 14 I/O124 (io), 15 I/O125 (io), 16 I/O126 (io), 17 I/O127 (io), 19 IN7 (in), 20 Y0 (in), 21 ~{RESET} (in), 23 GOE1 (in), 25 ~{BSCAN} (in), 26 TDI/IN0 (in), 28 I/O0 (io), 29 I/O1 (io), 30 I/O2 (io), 31 I/O3 (io), 32 I/O4 (io), 33 I/O5 (io), 34 I/O6 (io), 35 I/O7 (io), 37 I/O8 (io), 38 I/O9 (io), 39 I/O10 (io), 40 I/O11 (io), 41 I/O12 (io), 42 I/O13 (io), 44 I/O14 (io), 45 I/O15 (io), 47 I/O16 (io), 48 I/O17 (io), 49 I/O18 (io), 50 I/O19 (io), 51 I/O20 (io), 52 I/O21 (io), 53 I/O22 (io), 54 I/O23 (io), 56 I/O24 (io), 57 I/O25 (io), 58 I/O26 (io), 59 I/O27 (io), 60 I/O28 (io), 61 I/O29 (io), 62 I/O30 (io), 63 I/O31 (io), 66 TMS/IN1 (in), 67 IN6 (in), 70 I/O32 (io), 71 I/O33 (io), 72 I/O34 (io), 73 I/O35 (io), 74 I/O36 (io), 75 I/O37 (io), 76 I/O38 (io), 77 I/O39 (io), 79 I/O40 (io), 80 I/O41 (io), 81 I/O42 (io), 82 I/O43 (io), 83 I/O44 (io), 84 I/O45 (io), 85 I/O46 (io), 86 I/O47 (io), 88 I/O48 (io), 89 I/O49 (io), 91 I/O50 (io), 92 I/O51 (io), 93 I/O52 (io), 94 I/O53 (io), 95 I/O54 (io), 96 I/O55 (io), 98 I/O56 (io), 99 I/O57 (io), 100 I/O58 (io), 101 I/O59 (io), 102 I/O60 (io), 103 I/O61 (io), 104 I/O62 (io), 105 I/O63 (io), 107 TCK/IN3 (in), 108 Y2 (in), 110 GOE0 (in), 113 Y1 (in), 114 IN4 (in), 116 I/O64 (io), 117 I/O65 (io), 118 I/O66 (io), 119 I/O67 (io), 120 I/O68 (io), 121 I/O69 (io), 122 I/O70 (io), 123 I/O71 (io), 125 I/O72 (io), 126 I/O73 (io), 127 I/O74 (io), 128 I/O75 (io), 129 I/O76 (io), 130 I/O77 (io), 132 I/O78 (io), 133 I/O79 (io), 135 I/O80 (io), 136 I/O81 (io), 137 I/O82 (io), 138 I/O83 (io), 139 I/O84 (io), 140 I/O85 (io), 141 I/O86 (io), 142 I/O87 (io), 144 I/O88 (io), 145 I/O89 (io), 146 I/O90 (io), 147 I/O91 (io), 148 I/O92 (io), 149 I/O93 (io), 150 I/O94 (io), 151 I/O95 (io), 154 TDO/IN2 (io), 155 IN5 (in), 158 I/O96 (io), 159 I/O97 (io), 160 I/O98 (io), 161 I/O99 (io), 162 I/O100 (io), 163 I/O101 (io), 164 I/O102 (io), 165 I/O103 (io), 167 I/O104 (io), 168 I/O105 (io), 169 I/O106 (io), 170 I/O107 (io), 171 I/O108 (io), 172 I/O109 (io), 173 I/O110 (io), 174 I/O111 (io), 176 I/O112 (io)
part B pins: 2 VCC (power), 9 NC, 18 NC, 22 VCC (power), 24 GND (power), 27 NC, 36 NC, 43 VCC (power), 46 GND (power), 55 NC, 64 NC, 65 VCC (power), 68 GND (power), 69 NC, 78 NC, 87 GND (power), 90 VCC (power), 97 NC, 106 NC, 109 GND (power), 111 VCC (power), 112 NC, 115 NC, 124 NC, 131 VCC (power), 134 GND (power), 143 NC, 152 NC, 153 GND (power), 156 VCC (power), 157 NC, 166 NC, 175 GND (power)

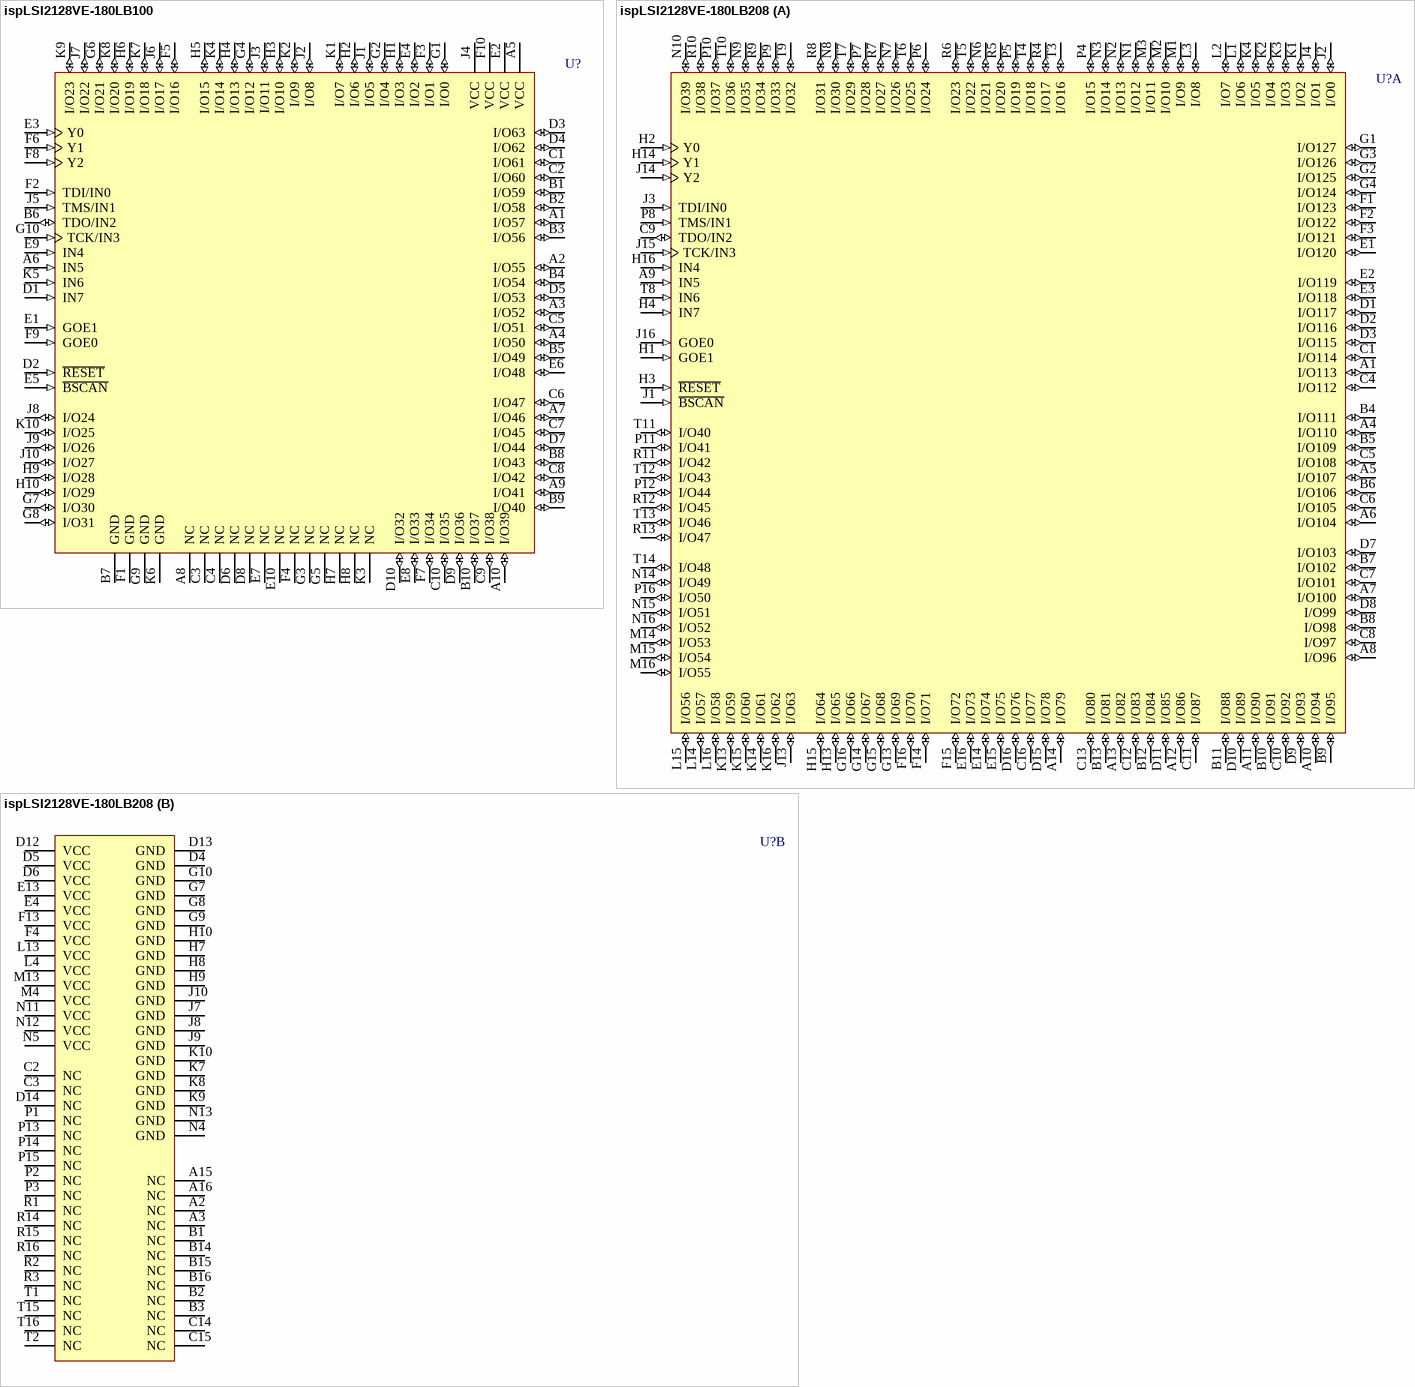
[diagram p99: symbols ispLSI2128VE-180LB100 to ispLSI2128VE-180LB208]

## ispLSI2128VE-180LB100
designator U?
3.3V In-System Programmable SuperFAST High Density PLD
footprint caBGA100 (BGA, 100-Leads, Body 10x10mm, Pitch 0.8mm)
3D model 2128VE-caBGA100 (100-Ball Chip Array Ball Grid Array (caBGA100))
pins: A1 I/O57 (io), A2 I/O55 (io), A3 I/O52 (io), A4 I/O50 (io), A5 VCC (power), A6 IN5 (in), A7 I/O46 (io), A8 NC, A9 I/O41 (io), A10 I/O39 (io), B1 I/O59 (io), B2 I/O58 (io), B3 I/O56 (io), B4 I/O54 (io), B5 I/O49 (io), B6 TDO/IN2 (io), B7 GND (power), B8 I/O43 (io), B9 I/O40 (io), B10 I/O37 (io), C1 I/O61 (io), C2 I/O60 (io), C3 NC, C4 NC, C5 I/O51 (io), C6 I/O47 (io), C7 I/O45 (io), C8 I/O42 (io), C9 I/O38 (io), C10 I/O35 (io), D1 IN7 (in), D2 ~{RESET} (in), D3 I/O63 (io), D4 I/O62 (io), D5 I/O53 (io), D6 NC, D7 I/O44 (io), D8 NC, D9 I/O36 (io), D10 I/O32 (io), E1 GOE1 (in), E2 VCC (power), E3 Y0 (in), E4 I/O2 (io), E5 ~{BSCAN} (in), E6 I/O48 (io), E7 NC, E8 I/O33 (io), E9 IN4 (in), E10 NC, F1 GND (power), F2 TDI/IN0 (in), F3 I/O1 (io), F4 NC, F5 I/O16 (io), F6 Y1 (in), F7 I/O34 (io), F8 Y2 (in), F9 GOE0 (in), F10 VCC (power), G1 I/O0 (io), G2 I/O4 (io), G3 NC, G4 I/O12 (io), G5 NC, G6 I/O21 (io), G7 I/O30 (io), G8 I/O31 (io), G9 GND (power), G10 TCK/IN3 (in), H1 I/O3 (io), H2 I/O6 (io), H3 I/O10 (io), H4 I/O13 (io), H5 I/O15 (io), H6 I/O19 (io), H7 NC, H8 NC, H9 I/O28 (io), H10 I/O29 (io), J1 I/O5 (io), J2 I/O8 (io), J3 I/O11 (io), J4 VCC (power), J5 TMS/IN1 (in), J6 I/O17 (io), J7 I/O22 (io), J8 I/O24 (io), J9 I/O26 (io), J10 I/O27 (io), K1 I/O7 (io), K2 I/O9 (io), K3 NC, K4 I/O14 (io), K5 IN6 (in), K6 GND (power), K7 I/O18 (io), K8 I/O20 (io), K9 I/O23 (io), K10 I/O25 (io)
